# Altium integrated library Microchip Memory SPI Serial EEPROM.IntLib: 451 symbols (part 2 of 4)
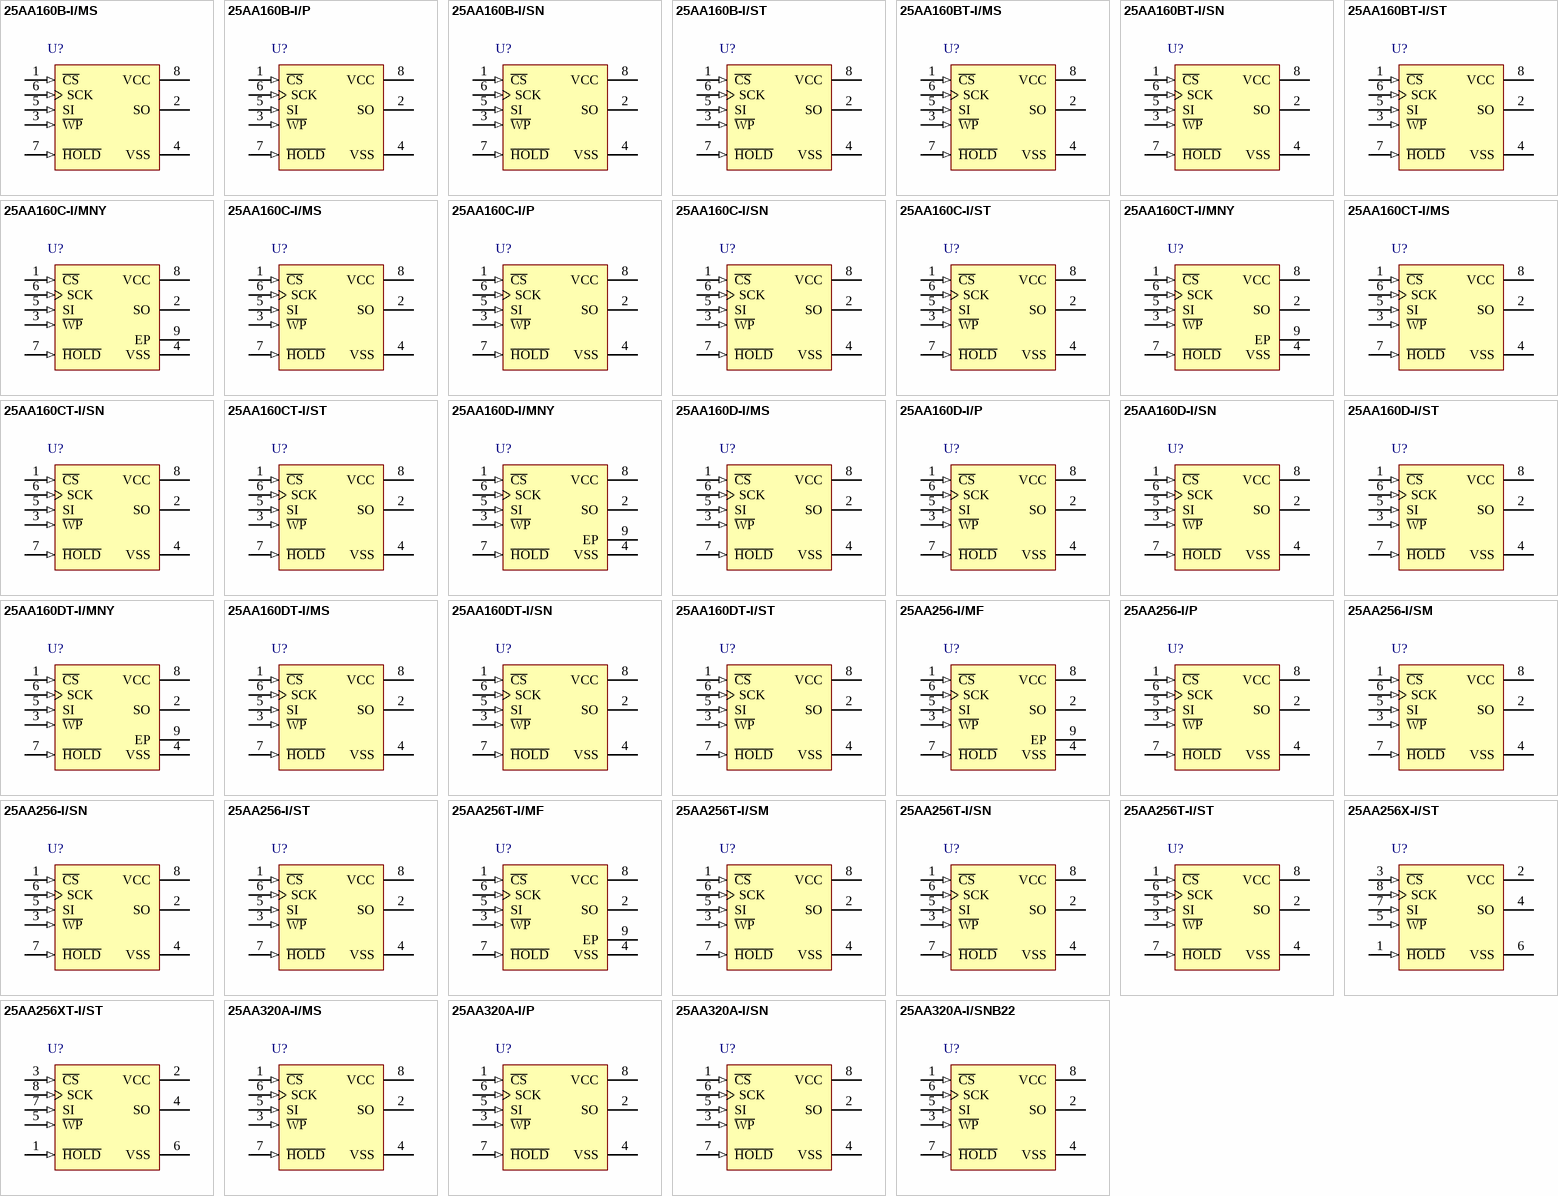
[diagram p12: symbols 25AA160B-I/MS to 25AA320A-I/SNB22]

## 25AA256T-I/SM
designator U?
256K SPI Bus Serial EEPROM, 8-Pin SOIC, Industrial Temperature, Tape and Reel
footprint SOIJ-SM8_N (SOP, 8-Leads, Body 5.2x5.2mm, Pitch 1.27mm, IPC Medium Density)
footprint SOIJ-SM8_L (SOP, 8-Leads, Body 5.2x5.2mm, Pitch 1.27mm, IPC High Density)
footprint SOIJ-SM8_M (SOP, 8-Leads, Body 5.2x5.2mm, Pitch 1.27mm, IPC Low Density)
pins: 1 ~{CS} (in), 2 SO (hiz), 3 ~{WP} (in), 4 VSS (power), 5 SI (in), 6 SCK (in), 7 ~{HOLD} (in), 8 VCC (power)

## 25AA256T-I/SN
designator U?
256K SPI Bus Serial EEPROM, 8-Pin SOIC, Industrial Temperature, Tape and Reel
footprint SOIC-SN8_N (SOIC, 8-Leads, Body 4.9x3.8mm, Pitch 1.27mm, IPC Medium Density)
footprint SOIC-SN8_L (SOIC, 8-Leads, Body 4.9x3.8mm, Pitch 1.27mm, IPC High Density)
footprint SOIC-SN8_M (SOIC, 8-Leads, Body 4.9x3.8mm, Pitch 1.27mm, IPC Low Density)
pins: 1 ~{CS} (in), 2 SO (hiz), 3 ~{WP} (in), 4 VSS (power), 5 SI (in), 6 SCK (in), 7 ~{HOLD} (in), 8 VCC (power)

## 25AA256T-I/ST
designator U?
256K SPI Bus Serial EEPROM, 8-Pin TSSOP, Industrial Temperature, Tape and Reel
footprint TSSOP-ST8_N (TSOP, 8-Leads, Body 3x4.4mm, Pitch 0.65mm, IPC Medium Density)
footprint TSSOP-ST8_L (TSOP, 8-Leads, Body 3x4.4mm, Pitch 0.65mm, IPC High Density)
footprint TSSOP-ST8_M (TSOP, 8-Leads, Body 3x4.4mm, Pitch 0.65mm, IPC Low Density)
pins: 1 ~{CS} (in), 2 SO (hiz), 3 ~{WP} (in), 4 VSS (power), 5 SI (in), 6 SCK (in), 7 ~{HOLD} (in), 8 VCC (power)

## 25AA256X-I/ST
designator U?
256K SPI Bus Serial EEPROM, 8-Pin TSSOP, Industrial Temperature
footprint TSSOP-ST8_N (TSOP, 8-Leads, Body 3x4.4mm, Pitch 0.65mm, IPC Medium Density)
footprint TSSOP-ST8_L (TSOP, 8-Leads, Body 3x4.4mm, Pitch 0.65mm, IPC High Density)
footprint TSSOP-ST8_M (TSOP, 8-Leads, Body 3x4.4mm, Pitch 0.65mm, IPC Low Density)
pins: 1 ~{HOLD} (in), 2 VCC (power), 3 ~{CS} (in), 4 SO (hiz), 5 ~{WP} (in), 6 VSS (power), 7 SI (in), 8 SCK (in)

## 25AA256XT-I/ST
designator U?
256K SPI Bus Serial EEPROM, 8-Pin TSSOP, Industrial Temperature, Tape and Reel
footprint TSSOP-ST8_N (TSOP, 8-Leads, Body 3x4.4mm, Pitch 0.65mm, IPC Medium Density)
footprint TSSOP-ST8_L (TSOP, 8-Leads, Body 3x4.4mm, Pitch 0.65mm, IPC High Density)
footprint TSSOP-ST8_M (TSOP, 8-Leads, Body 3x4.4mm, Pitch 0.65mm, IPC Low Density)
pins: 1 ~{HOLD} (in), 2 VCC (power), 3 ~{CS} (in), 4 SO (hiz), 5 ~{WP} (in), 6 VSS (power), 7 SI (in), 8 SCK (in)

## 25AA320A-I/MS
designator U?
32K SPI Bus Serial EEPROM, 8-Pin MSOP, Industrial Temperature
footprint MSOP-MS8_N (TSOP, 8-Leads, Body 3x3mm, Pitch 0.65mm, IPC Medium Density)
footprint MSOP-MS8_L (TSOP, 8-Leads, Body 3x3mm, Pitch 0.65mm, IPC High Density)
footprint MSOP-MS8_M (TSOP, 8-Leads, Body 3x3mm, Pitch 0.65mm, IPC Low Density)
pins: 1 ~{CS} (in), 2 SO (hiz), 3 ~{WP} (in), 4 VSS (power), 5 SI (in), 6 SCK (in), 7 ~{HOLD} (in), 8 VCC (power)

## 25AA320A-I/P
designator U?
32K SPI Bus Serial EEPROM, 8-Pin PDIP, Industrial Temperature
footprint PDIP300-P8 (DIP, 8-Leads, Row Spacing 7.62mm, Pitch 2.54mm, Body 9.5x6.6mm)
pins: 1 ~{CS} (in), 2 SO (hiz), 3 ~{WP} (in), 4 VSS (power), 5 SI (in), 6 SCK (in), 7 ~{HOLD} (in), 8 VCC (power)

## 25AA320A-I/SN
designator U?
32K SPI Bus Serial EEPROM, 8-Pin SOIC, Industrial Temperature
footprint SOIC-SN8_N (SOIC, 8-Leads, Body 4.9x3.8mm, Pitch 1.27mm, IPC Medium Density)
footprint SOIC-SN8_L (SOIC, 8-Leads, Body 4.9x3.8mm, Pitch 1.27mm, IPC High Density)
footprint SOIC-SN8_M (SOIC, 8-Leads, Body 4.9x3.8mm, Pitch 1.27mm, IPC Low Density)
pins: 1 ~{CS} (in), 2 SO (hiz), 3 ~{WP} (in), 4 VSS (power), 5 SI (in), 6 SCK (in), 7 ~{HOLD} (in), 8 VCC (power)

## 25AA320A-I/SNB22
designator U?
32K SPI Bus Serial EEPROM, 8-Pin SOIC, Industrial Temperature
footprint SOIC-SN8_N (SOIC, 8-Leads, Body 4.9x3.8mm, Pitch 1.27mm, IPC Medium Density)
footprint SOIC-SN8_L (SOIC, 8-Leads, Body 4.9x3.8mm, Pitch 1.27mm, IPC High Density)
footprint SOIC-SN8_M (SOIC, 8-Leads, Body 4.9x3.8mm, Pitch 1.27mm, IPC Low Density)
pins: 1 ~{CS} (in), 2 SO (hiz), 3 ~{WP} (in), 4 VSS (power), 5 SI (in), 6 SCK (in), 7 ~{HOLD} (in), 8 VCC (power)

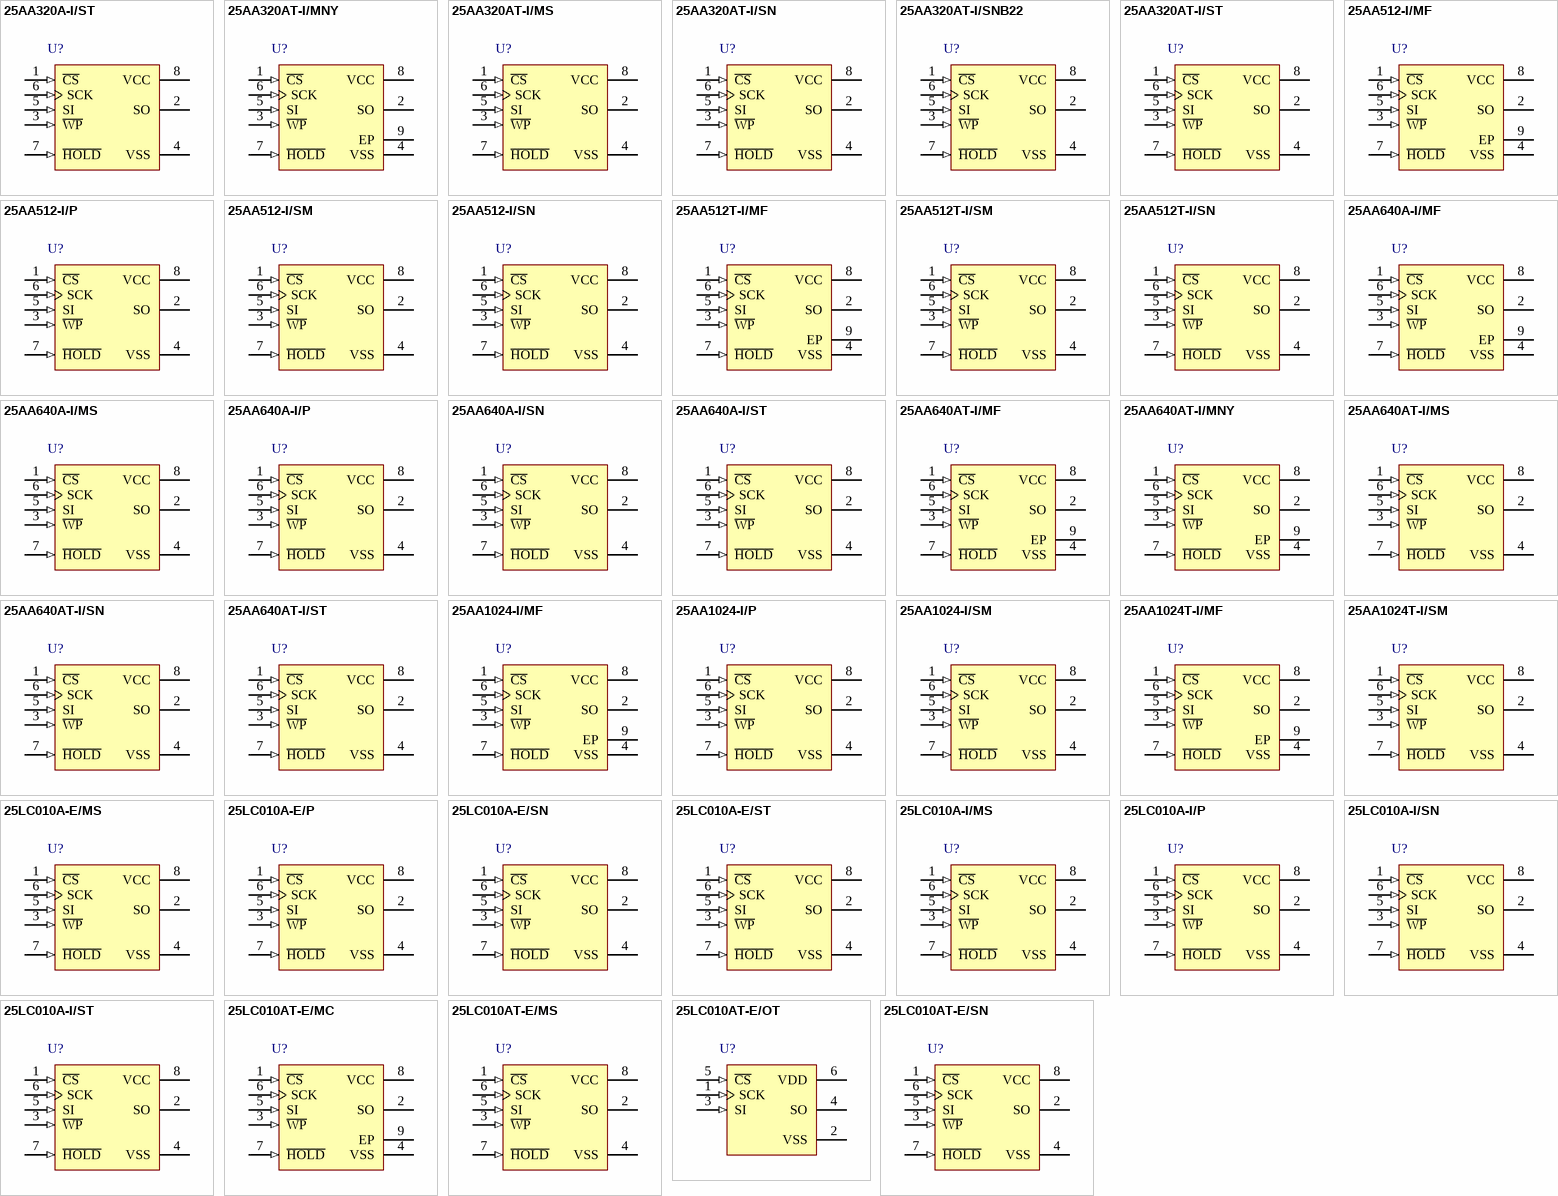
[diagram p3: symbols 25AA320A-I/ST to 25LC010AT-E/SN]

## 25AA320A-I/ST
designator U?
32K SPI Bus Serial EEPROM, 8-Pin TSSOP, Industrial Temperature
footprint TSSOP-ST8_N (TSOP, 8-Leads, Body 3x4.4mm, Pitch 0.65mm, IPC Medium Density)
footprint TSSOP-ST8_L (TSOP, 8-Leads, Body 3x4.4mm, Pitch 0.65mm, IPC High Density)
footprint TSSOP-ST8_M (TSOP, 8-Leads, Body 3x4.4mm, Pitch 0.65mm, IPC Low Density)
pins: 1 ~{CS} (in), 2 SO (hiz), 3 ~{WP} (in), 4 VSS (power), 5 SI (in), 6 SCK (in), 7 ~{HOLD} (in), 8 VCC (power)

## 25AA320AT-I/MNY
designator U?
32K SPI Bus Serial EEPROM, 8-Pin TDFN, Industrial Temperature, Tape and Reel
footprint TDFN-MN8 (SON, 8-Leads, Body 2x3mm, Pitch 0.5mm, Microchip Recommended)
pins: 1 ~{CS} (in), 2 SO (hiz), 3 ~{WP} (in), 4 VSS (power), 5 SI (in), 6 SCK (in), 7 ~{HOLD} (in), 8 VCC (power), 9 EP

## 25AA320AT-I/MS
designator U?
32K SPI Bus Serial EEPROM, 8-Pin MSOP, Industrial Temperature, Tape and Reel
footprint MSOP-MS8_N (TSOP, 8-Leads, Body 3x3mm, Pitch 0.65mm, IPC Medium Density)
footprint MSOP-MS8_L (TSOP, 8-Leads, Body 3x3mm, Pitch 0.65mm, IPC High Density)
footprint MSOP-MS8_M (TSOP, 8-Leads, Body 3x3mm, Pitch 0.65mm, IPC Low Density)
pins: 1 ~{CS} (in), 2 SO (hiz), 3 ~{WP} (in), 4 VSS (power), 5 SI (in), 6 SCK (in), 7 ~{HOLD} (in), 8 VCC (power)

## 25AA320AT-I/SN
designator U?
32K SPI Bus Serial EEPROM, 8-Pin SOIC, Industrial Temperature, Tape and Reel
footprint SOIC-SN8_N (SOIC, 8-Leads, Body 4.9x3.8mm, Pitch 1.27mm, IPC Medium Density)
footprint SOIC-SN8_L (SOIC, 8-Leads, Body 4.9x3.8mm, Pitch 1.27mm, IPC High Density)
footprint SOIC-SN8_M (SOIC, 8-Leads, Body 4.9x3.8mm, Pitch 1.27mm, IPC Low Density)
pins: 1 ~{CS} (in), 2 SO (hiz), 3 ~{WP} (in), 4 VSS (power), 5 SI (in), 6 SCK (in), 7 ~{HOLD} (in), 8 VCC (power)

## 25AA320AT-I/SNB22
designator U?
32K SPI Bus Serial EEPROM, 8-Pin SOIC, Industrial Temperature, Tape and Reel
footprint SOIC-SN8_N (SOIC, 8-Leads, Body 4.9x3.8mm, Pitch 1.27mm, IPC Medium Density)
footprint SOIC-SN8_L (SOIC, 8-Leads, Body 4.9x3.8mm, Pitch 1.27mm, IPC High Density)
footprint SOIC-SN8_M (SOIC, 8-Leads, Body 4.9x3.8mm, Pitch 1.27mm, IPC Low Density)
pins: 1 ~{CS} (in), 2 SO (hiz), 3 ~{WP} (in), 4 VSS (power), 5 SI (in), 6 SCK (in), 7 ~{HOLD} (in), 8 VCC (power)

## 25AA320AT-I/ST
designator U?
32K SPI Bus Serial EEPROM, 8-Pin TSSOP, Industrial Temperature, Tape and Reel
footprint TSSOP-ST8_N (TSOP, 8-Leads, Body 3x4.4mm, Pitch 0.65mm, IPC Medium Density)
footprint TSSOP-ST8_L (TSOP, 8-Leads, Body 3x4.4mm, Pitch 0.65mm, IPC High Density)
footprint TSSOP-ST8_M (TSOP, 8-Leads, Body 3x4.4mm, Pitch 0.65mm, IPC Low Density)
pins: 1 ~{CS} (in), 2 SO (hiz), 3 ~{WP} (in), 4 VSS (power), 5 SI (in), 6 SCK (in), 7 ~{HOLD} (in), 8 VCC (power)

## 25AA512-I/MF
designator U?
512 Kbit SPI Bus Serial EEPROM, 8-Pin DFN, Industrial Temperature
footprint DFNS-MF8_PS (SON, 8-Leads, Body 5x6mm, Pitch 1.27mm)
pins: 1 ~{CS} (in), 2 SO (hiz), 3 ~{WP} (in), 4 VSS (power), 5 SI (in), 6 SCK (in), 7 ~{HOLD} (in), 8 VCC (power), 9 EP

## 25AA512-I/P
designator U?
512 Kbit SPI Bus Serial EEPROM, 8-Pin PDIP, Industrial Temperature
footprint PDIP300-P8 (DIP, 8-Leads, Row Spacing 7.62mm, Pitch 2.54mm, Body 9.5x6.6mm)
pins: 1 ~{CS} (in), 2 SO (hiz), 3 ~{WP} (in), 4 VSS (power), 5 SI (in), 6 SCK (in), 7 ~{HOLD} (in), 8 VCC (power)

## 25AA512-I/SM
designator U?
512 Kbit SPI Bus Serial EEPROM, 8-Pin SOIC, Industrial Temperature
footprint SOIJ-SM8_N (SOP, 8-Leads, Body 5.2x5.2mm, Pitch 1.27mm, IPC Medium Density)
footprint SOIJ-SM8_L (SOP, 8-Leads, Body 5.2x5.2mm, Pitch 1.27mm, IPC High Density)
footprint SOIJ-SM8_M (SOP, 8-Leads, Body 5.2x5.2mm, Pitch 1.27mm, IPC Low Density)
pins: 1 ~{CS} (in), 2 SO (hiz), 3 ~{WP} (in), 4 VSS (power), 5 SI (in), 6 SCK (in), 7 ~{HOLD} (in), 8 VCC (power)

## 25AA512-I/SN
designator U?
512 Kbit SPI Bus Serial EEPROM, 8-Pin SOIC, Industrial Temperature
footprint SOIC-SN8_N (SOIC, 8-Leads, Body 4.9x3.8mm, Pitch 1.27mm, IPC Medium Density)
footprint SOIC-SN8_L (SOIC, 8-Leads, Body 4.9x3.8mm, Pitch 1.27mm, IPC High Density)
footprint SOIC-SN8_M (SOIC, 8-Leads, Body 4.9x3.8mm, Pitch 1.27mm, IPC Low Density)
pins: 1 ~{CS} (in), 2 SO (hiz), 3 ~{WP} (in), 4 VSS (power), 5 SI (in), 6 SCK (in), 7 ~{HOLD} (in), 8 VCC (power)

## 25AA512T-I/MF
designator U?
512 Kbit SPI Bus Serial EEPROM, 8-Pin DFN, Industrial Temperature, Tape and Reel
footprint DFNS-MF8_PS (SON, 8-Leads, Body 5x6mm, Pitch 1.27mm)
pins: 1 ~{CS} (in), 2 SO (hiz), 3 ~{WP} (in), 4 VSS (power), 5 SI (in), 6 SCK (in), 7 ~{HOLD} (in), 8 VCC (power), 9 EP

## 25AA512T-I/SM
designator U?
512 Kbit SPI Bus Serial EEPROM, 8-Pin SOIC, Industrial Temperature, Tape and Reel
footprint SOIJ-SM8_N (SOP, 8-Leads, Body 5.2x5.2mm, Pitch 1.27mm, IPC Medium Density)
footprint SOIJ-SM8_L (SOP, 8-Leads, Body 5.2x5.2mm, Pitch 1.27mm, IPC High Density)
footprint SOIJ-SM8_M (SOP, 8-Leads, Body 5.2x5.2mm, Pitch 1.27mm, IPC Low Density)
pins: 1 ~{CS} (in), 2 SO (hiz), 3 ~{WP} (in), 4 VSS (power), 5 SI (in), 6 SCK (in), 7 ~{HOLD} (in), 8 VCC (power)

## 25AA512T-I/SN
designator U?
512 Kbit SPI Bus Serial EEPROM, 8-Pin SOIC, Industrial Temperature, Tape and Reel
footprint SOIC-SN8_N (SOIC, 8-Leads, Body 4.9x3.8mm, Pitch 1.27mm, IPC Medium Density)
footprint SOIC-SN8_L (SOIC, 8-Leads, Body 4.9x3.8mm, Pitch 1.27mm, IPC High Density)
footprint SOIC-SN8_M (SOIC, 8-Leads, Body 4.9x3.8mm, Pitch 1.27mm, IPC Low Density)
pins: 1 ~{CS} (in), 2 SO (hiz), 3 ~{WP} (in), 4 VSS (power), 5 SI (in), 6 SCK (in), 7 ~{HOLD} (in), 8 VCC (power)

## 25AA640A-I/MF
designator U?
64K SPI Bus Serial EEPROM, 8-Pin DFN, Industrial Temperature
footprint DFNS-MF8_PS (SON, 8-Leads, Body 5x6mm, Pitch 1.27mm)
pins: 1 ~{CS} (in), 2 SO (hiz), 3 ~{WP} (in), 4 VSS (power), 5 SI (in), 6 SCK (in), 7 ~{HOLD} (in), 8 VCC (power), 9 EP

## 25AA640A-I/MS
designator U?
64K SPI Bus Serial EEPROM, 8-Pin MSOP, Industrial Temperature
footprint MSOP-MS8_N (TSOP, 8-Leads, Body 3x3mm, Pitch 0.65mm, IPC Medium Density)
footprint MSOP-MS8_L (TSOP, 8-Leads, Body 3x3mm, Pitch 0.65mm, IPC High Density)
footprint MSOP-MS8_M (TSOP, 8-Leads, Body 3x3mm, Pitch 0.65mm, IPC Low Density)
pins: 1 ~{CS} (in), 2 SO (hiz), 3 ~{WP} (in), 4 VSS (power), 5 SI (in), 6 SCK (in), 7 ~{HOLD} (in), 8 VCC (power)

## 25AA640A-I/P
designator U?
64K SPI Bus Serial EEPROM, 8-Pin PDIP, Industrial Temperature
footprint PDIP300-P8 (DIP, 8-Leads, Row Spacing 7.62mm, Pitch 2.54mm, Body 9.5x6.6mm)
pins: 1 ~{CS} (in), 2 SO (hiz), 3 ~{WP} (in), 4 VSS (power), 5 SI (in), 6 SCK (in), 7 ~{HOLD} (in), 8 VCC (power)

## 25AA640A-I/SN
designator U?
64K SPI Bus Serial EEPROM, 8-Pin SOIC, Industrial Temperature
footprint SOIC-SN8_N (SOIC, 8-Leads, Body 4.9x3.8mm, Pitch 1.27mm, IPC Medium Density)
footprint SOIC-SN8_L (SOIC, 8-Leads, Body 4.9x3.8mm, Pitch 1.27mm, IPC High Density)
footprint SOIC-SN8_M (SOIC, 8-Leads, Body 4.9x3.8mm, Pitch 1.27mm, IPC Low Density)
pins: 1 ~{CS} (in), 2 SO (hiz), 3 ~{WP} (in), 4 VSS (power), 5 SI (in), 6 SCK (in), 7 ~{HOLD} (in), 8 VCC (power)

## 25AA640A-I/ST
designator U?
64K SPI Bus Serial EEPROM, 8-Pin TSSOP, Industrial Temperature
footprint TSSOP-ST8_N (TSOP, 8-Leads, Body 3x4.4mm, Pitch 0.65mm, IPC Medium Density)
footprint TSSOP-ST8_L (TSOP, 8-Leads, Body 3x4.4mm, Pitch 0.65mm, IPC High Density)
footprint TSSOP-ST8_M (TSOP, 8-Leads, Body 3x4.4mm, Pitch 0.65mm, IPC Low Density)
pins: 1 ~{CS} (in), 2 SO (hiz), 3 ~{WP} (in), 4 VSS (power), 5 SI (in), 6 SCK (in), 7 ~{HOLD} (in), 8 VCC (power)

## 25AA640AT-I/MF
designator U?
64K SPI Bus Serial EEPROM, 8-Pin DFN, Industrial Temperature, Tape and Reel
footprint DFNS-MF8_PS (SON, 8-Leads, Body 5x6mm, Pitch 1.27mm)
pins: 1 ~{CS} (in), 2 SO (hiz), 3 ~{WP} (in), 4 VSS (power), 5 SI (in), 6 SCK (in), 7 ~{HOLD} (in), 8 VCC (power), 9 EP

## 25AA640AT-I/MNY
designator U?
64K SPI Bus Serial EEPROM, 8-Pin TDFN, Industrial Temperature, Tape and Reel
footprint TDFN-MN8 (SON, 8-Leads, Body 2x3mm, Pitch 0.5mm, Microchip Recommended)
pins: 1 ~{CS} (in), 2 SO (hiz), 3 ~{WP} (in), 4 VSS (power), 5 SI (in), 6 SCK (in), 7 ~{HOLD} (in), 8 VCC (power), 9 EP

## 25AA640AT-I/MS
designator U?
64K SPI Bus Serial EEPROM, 8-Pin MSOP, Industrial Temperature, Tape and Reel
footprint MSOP-MS8_N (TSOP, 8-Leads, Body 3x3mm, Pitch 0.65mm, IPC Medium Density)
footprint MSOP-MS8_L (TSOP, 8-Leads, Body 3x3mm, Pitch 0.65mm, IPC High Density)
footprint MSOP-MS8_M (TSOP, 8-Leads, Body 3x3mm, Pitch 0.65mm, IPC Low Density)
pins: 1 ~{CS} (in), 2 SO (hiz), 3 ~{WP} (in), 4 VSS (power), 5 SI (in), 6 SCK (in), 7 ~{HOLD} (in), 8 VCC (power)

## 25AA640AT-I/SN
designator U?
64K SPI Bus Serial EEPROM, 8-Pin SOIC, Industrial Temperature, Tape and Reel
footprint SOIC-SN8_N (SOIC, 8-Leads, Body 4.9x3.8mm, Pitch 1.27mm, IPC Medium Density)
footprint SOIC-SN8_L (SOIC, 8-Leads, Body 4.9x3.8mm, Pitch 1.27mm, IPC High Density)
footprint SOIC-SN8_M (SOIC, 8-Leads, Body 4.9x3.8mm, Pitch 1.27mm, IPC Low Density)
pins: 1 ~{CS} (in), 2 SO (hiz), 3 ~{WP} (in), 4 VSS (power), 5 SI (in), 6 SCK (in), 7 ~{HOLD} (in), 8 VCC (power)

## 25AA640AT-I/ST
designator U?
64K SPI Bus Serial EEPROM, 8-Pin TSSOP, Industrial Temperature, Tape and Reel
footprint TSSOP-ST8_N (TSOP, 8-Leads, Body 3x4.4mm, Pitch 0.65mm, IPC Medium Density)
footprint TSSOP-ST8_L (TSOP, 8-Leads, Body 3x4.4mm, Pitch 0.65mm, IPC High Density)
footprint TSSOP-ST8_M (TSOP, 8-Leads, Body 3x4.4mm, Pitch 0.65mm, IPC Low Density)
pins: 1 ~{CS} (in), 2 SO (hiz), 3 ~{WP} (in), 4 VSS (power), 5 SI (in), 6 SCK (in), 7 ~{HOLD} (in), 8 VCC (power)

## 25AA1024-I/MF
designator U?
1 Mbit SPI Bus Serial EEPROM, 8-Pin DFN, Industrial Temperature
footprint DFNS-MF8_PS (SON, 8-Leads, Body 5x6mm, Pitch 1.27mm)
pins: 1 ~{CS} (in), 2 SO (hiz), 3 ~{WP} (in), 4 VSS (power), 5 SI (in), 6 SCK (in), 7 ~{HOLD} (in), 8 VCC (power), 9 EP

## 25AA1024-I/P
designator U?
1 Mbit SPI Bus Serial EEPROM, 8-Pin PDIP, Industrial Temperature
footprint PDIP300-P8 (DIP, 8-Leads, Row Spacing 7.62mm, Pitch 2.54mm, Body 9.5x6.6mm)
pins: 1 ~{CS} (in), 2 SO (hiz), 3 ~{WP} (in), 4 VSS (power), 5 SI (in), 6 SCK (in), 7 ~{HOLD} (in), 8 VCC (power)

## 25AA1024-I/SM
designator U?
1 Mbit SPI Bus Serial EEPROM, 8-Pin SOIC, Industrial Temperature
footprint SOIJ-SM8_N (SOP, 8-Leads, Body 5.2x5.2mm, Pitch 1.27mm, IPC Medium Density)
footprint SOIJ-SM8_L (SOP, 8-Leads, Body 5.2x5.2mm, Pitch 1.27mm, IPC High Density)
footprint SOIJ-SM8_M (SOP, 8-Leads, Body 5.2x5.2mm, Pitch 1.27mm, IPC Low Density)
pins: 1 ~{CS} (in), 2 SO (hiz), 3 ~{WP} (in), 4 VSS (power), 5 SI (in), 6 SCK (in), 7 ~{HOLD} (in), 8 VCC (power)

## 25AA1024T-I/MF
designator U?
1 Mbit SPI Bus Serial EEPROM, 8-Pin DFN, Industrial Temperature, Tape and Reel
footprint DFNS-MF8_PS (SON, 8-Leads, Body 5x6mm, Pitch 1.27mm)
pins: 1 ~{CS} (in), 2 SO (hiz), 3 ~{WP} (in), 4 VSS (power), 5 SI (in), 6 SCK (in), 7 ~{HOLD} (in), 8 VCC (power), 9 EP

## 25AA1024T-I/SM
designator U?
1 Mbit SPI Bus Serial EEPROM, 8-Pin SOIC, Industrial Temperature, Tape and Reel
footprint SOIJ-SM8_N (SOP, 8-Leads, Body 5.2x5.2mm, Pitch 1.27mm, IPC Medium Density)
footprint SOIJ-SM8_L (SOP, 8-Leads, Body 5.2x5.2mm, Pitch 1.27mm, IPC High Density)
footprint SOIJ-SM8_M (SOP, 8-Leads, Body 5.2x5.2mm, Pitch 1.27mm, IPC Low Density)
pins: 1 ~{CS} (in), 2 SO (hiz), 3 ~{WP} (in), 4 VSS (power), 5 SI (in), 6 SCK (in), 7 ~{HOLD} (in), 8 VCC (power)

## 25LC010A-E/MS
designator U?
1K SPI Bus Serial EEPROM, 8-Pin MSOP, Extended Temperature
footprint MSOP-MS8_N (TSOP, 8-Leads, Body 3x3mm, Pitch 0.65mm, IPC Medium Density)
footprint MSOP-MS8_L (TSOP, 8-Leads, Body 3x3mm, Pitch 0.65mm, IPC High Density)
footprint MSOP-MS8_M (TSOP, 8-Leads, Body 3x3mm, Pitch 0.65mm, IPC Low Density)
pins: 1 ~{CS} (in), 2 SO (hiz), 3 ~{WP} (in), 4 VSS (power), 5 SI (in), 6 SCK (in), 7 ~{HOLD} (in), 8 VCC (power)

## 25LC010A-E/P
designator U?
1K SPI Bus Serial EEPROM, 8-Pin PDIP, Extended Temperature
footprint PDIP300-P8 (DIP, 8-Leads, Row Spacing 7.62mm, Pitch 2.54mm, Body 9.5x6.6mm)
pins: 1 ~{CS} (in), 2 SO (hiz), 3 ~{WP} (in), 4 VSS (power), 5 SI (in), 6 SCK (in), 7 ~{HOLD} (in), 8 VCC (power)

## 25LC010A-E/SN
designator U?
1K SPI Bus Serial EEPROM, 8-Pin SOIC, Extended Temperature
footprint SOIC-SN8_N (SOIC, 8-Leads, Body 4.9x3.8mm, Pitch 1.27mm, IPC Medium Density)
footprint SOIC-SN8_L (SOIC, 8-Leads, Body 4.9x3.8mm, Pitch 1.27mm, IPC High Density)
footprint SOIC-SN8_M (SOIC, 8-Leads, Body 4.9x3.8mm, Pitch 1.27mm, IPC Low Density)
pins: 1 ~{CS} (in), 2 SO (hiz), 3 ~{WP} (in), 4 VSS (power), 5 SI (in), 6 SCK (in), 7 ~{HOLD} (in), 8 VCC (power)

## 25LC010A-E/ST
designator U?
1K SPI Bus Serial EEPROM, 8-Pin TSSOP, Extended Temperature
footprint TSSOP-ST8_N (TSOP, 8-Leads, Body 3x4.4mm, Pitch 0.65mm, IPC Medium Density)
footprint TSSOP-ST8_L (TSOP, 8-Leads, Body 3x4.4mm, Pitch 0.65mm, IPC High Density)
footprint TSSOP-ST8_M (TSOP, 8-Leads, Body 3x4.4mm, Pitch 0.65mm, IPC Low Density)
pins: 1 ~{CS} (in), 2 SO (hiz), 3 ~{WP} (in), 4 VSS (power), 5 SI (in), 6 SCK (in), 7 ~{HOLD} (in), 8 VCC (power)

## 25LC010A-I/MS
designator U?
1K SPI Bus Serial EEPROM, 8-Pin MSOP, Industrial Temperature
footprint MSOP-MS8_N (TSOP, 8-Leads, Body 3x3mm, Pitch 0.65mm, IPC Medium Density)
footprint MSOP-MS8_L (TSOP, 8-Leads, Body 3x3mm, Pitch 0.65mm, IPC High Density)
footprint MSOP-MS8_M (TSOP, 8-Leads, Body 3x3mm, Pitch 0.65mm, IPC Low Density)
pins: 1 ~{CS} (in), 2 SO (hiz), 3 ~{WP} (in), 4 VSS (power), 5 SI (in), 6 SCK (in), 7 ~{HOLD} (in), 8 VCC (power)

## 25LC010A-I/P
designator U?
1K SPI Bus Serial EEPROM, 8-Pin PDIP, Industrial Temperature
footprint PDIP300-P8 (DIP, 8-Leads, Row Spacing 7.62mm, Pitch 2.54mm, Body 9.5x6.6mm)
pins: 1 ~{CS} (in), 2 SO (hiz), 3 ~{WP} (in), 4 VSS (power), 5 SI (in), 6 SCK (in), 7 ~{HOLD} (in), 8 VCC (power)

## 25LC010A-I/SN
designator U?
1K SPI Bus Serial EEPROM, 8-Pin SOIC, Industrial Temperature
footprint SOIC-SN8_N (SOIC, 8-Leads, Body 4.9x3.8mm, Pitch 1.27mm, IPC Medium Density)
footprint SOIC-SN8_L (SOIC, 8-Leads, Body 4.9x3.8mm, Pitch 1.27mm, IPC High Density)
footprint SOIC-SN8_M (SOIC, 8-Leads, Body 4.9x3.8mm, Pitch 1.27mm, IPC Low Density)
pins: 1 ~{CS} (in), 2 SO (hiz), 3 ~{WP} (in), 4 VSS (power), 5 SI (in), 6 SCK (in), 7 ~{HOLD} (in), 8 VCC (power)

## 25LC010A-I/ST
designator U?
1K SPI Bus Serial EEPROM, 8-Pin TSSOP, Industrial Temperature
footprint TSSOP-ST8_N (TSOP, 8-Leads, Body 3x4.4mm, Pitch 0.65mm, IPC Medium Density)
footprint TSSOP-ST8_L (TSOP, 8-Leads, Body 3x4.4mm, Pitch 0.65mm, IPC High Density)
footprint TSSOP-ST8_M (TSOP, 8-Leads, Body 3x4.4mm, Pitch 0.65mm, IPC Low Density)
pins: 1 ~{CS} (in), 2 SO (hiz), 3 ~{WP} (in), 4 VSS (power), 5 SI (in), 6 SCK (in), 7 ~{HOLD} (in), 8 VCC (power)

## 25LC010AT-E/MC
designator U?
1K SPI Bus Serial EEPROM, 8-Pin DFN, Extended Temperature, Tape and Reel
footprint DFN-MC8 (SON, 8-Leads, Body 2x3mm, Pitch 0.5mm, Microchip Recommended)
pins: 1 ~{CS} (in), 2 SO (hiz), 3 ~{WP} (in), 4 VSS (power), 5 SI (in), 6 SCK (in), 7 ~{HOLD} (in), 8 VCC (power), 9 EP

## 25LC010AT-E/MS
designator U?
1K SPI Bus Serial EEPROM, 8-Pin MSOP, Extended Temperature, Tape and Reel
footprint MSOP-MS8_N (TSOP, 8-Leads, Body 3x3mm, Pitch 0.65mm, IPC Medium Density)
footprint MSOP-MS8_L (TSOP, 8-Leads, Body 3x3mm, Pitch 0.65mm, IPC High Density)
footprint MSOP-MS8_M (TSOP, 8-Leads, Body 3x3mm, Pitch 0.65mm, IPC Low Density)
pins: 1 ~{CS} (in), 2 SO (hiz), 3 ~{WP} (in), 4 VSS (power), 5 SI (in), 6 SCK (in), 7 ~{HOLD} (in), 8 VCC (power)

## 25LC010AT-E/OT
designator U?
1K SPI Bus Serial EEPROM, 6-Pin SOT-23, Extended Temperature, Tape and Reel
footprint SOT-23-OT6_N (SOT23, 6-Leads, Body 2.9x1.6mm, Pitch 0.95mm, Lead Span 2.7mm, IPC Medium Density)
footprint SOT-23-OT6_L (SOT23, 6-Leads, Body 2.9x1.6mm, Pitch 0.95mm, Lead Span 2.7mm, IPC High Density)
footprint SOT-23-OT6_M (SOT23, 6-Leads, Body 2.9x1.6mm, Pitch 0.95mm, Lead Span 2.7mm, IPC Low Density)
pins: 1 SCK (in), 2 VSS (power), 3 SI (in), 4 SO (hiz), 5 ~{CS} (in), 6 VDD (power)

## 25LC010AT-E/SN
designator U?
1K SPI Bus Serial EEPROM, 8-Pin SOIC, Extended Temperature, Tape and Reel
footprint SOIC-SN8_N (SOIC, 8-Leads, Body 4.9x3.8mm, Pitch 1.27mm, IPC Medium Density)
footprint SOIC-SN8_L (SOIC, 8-Leads, Body 4.9x3.8mm, Pitch 1.27mm, IPC High Density)
footprint SOIC-SN8_M (SOIC, 8-Leads, Body 4.9x3.8mm, Pitch 1.27mm, IPC Low Density)
pins: 1 ~{CS} (in), 2 SO (hiz), 3 ~{WP} (in), 4 VSS (power), 5 SI (in), 6 SCK (in), 7 ~{HOLD} (in), 8 VCC (power)

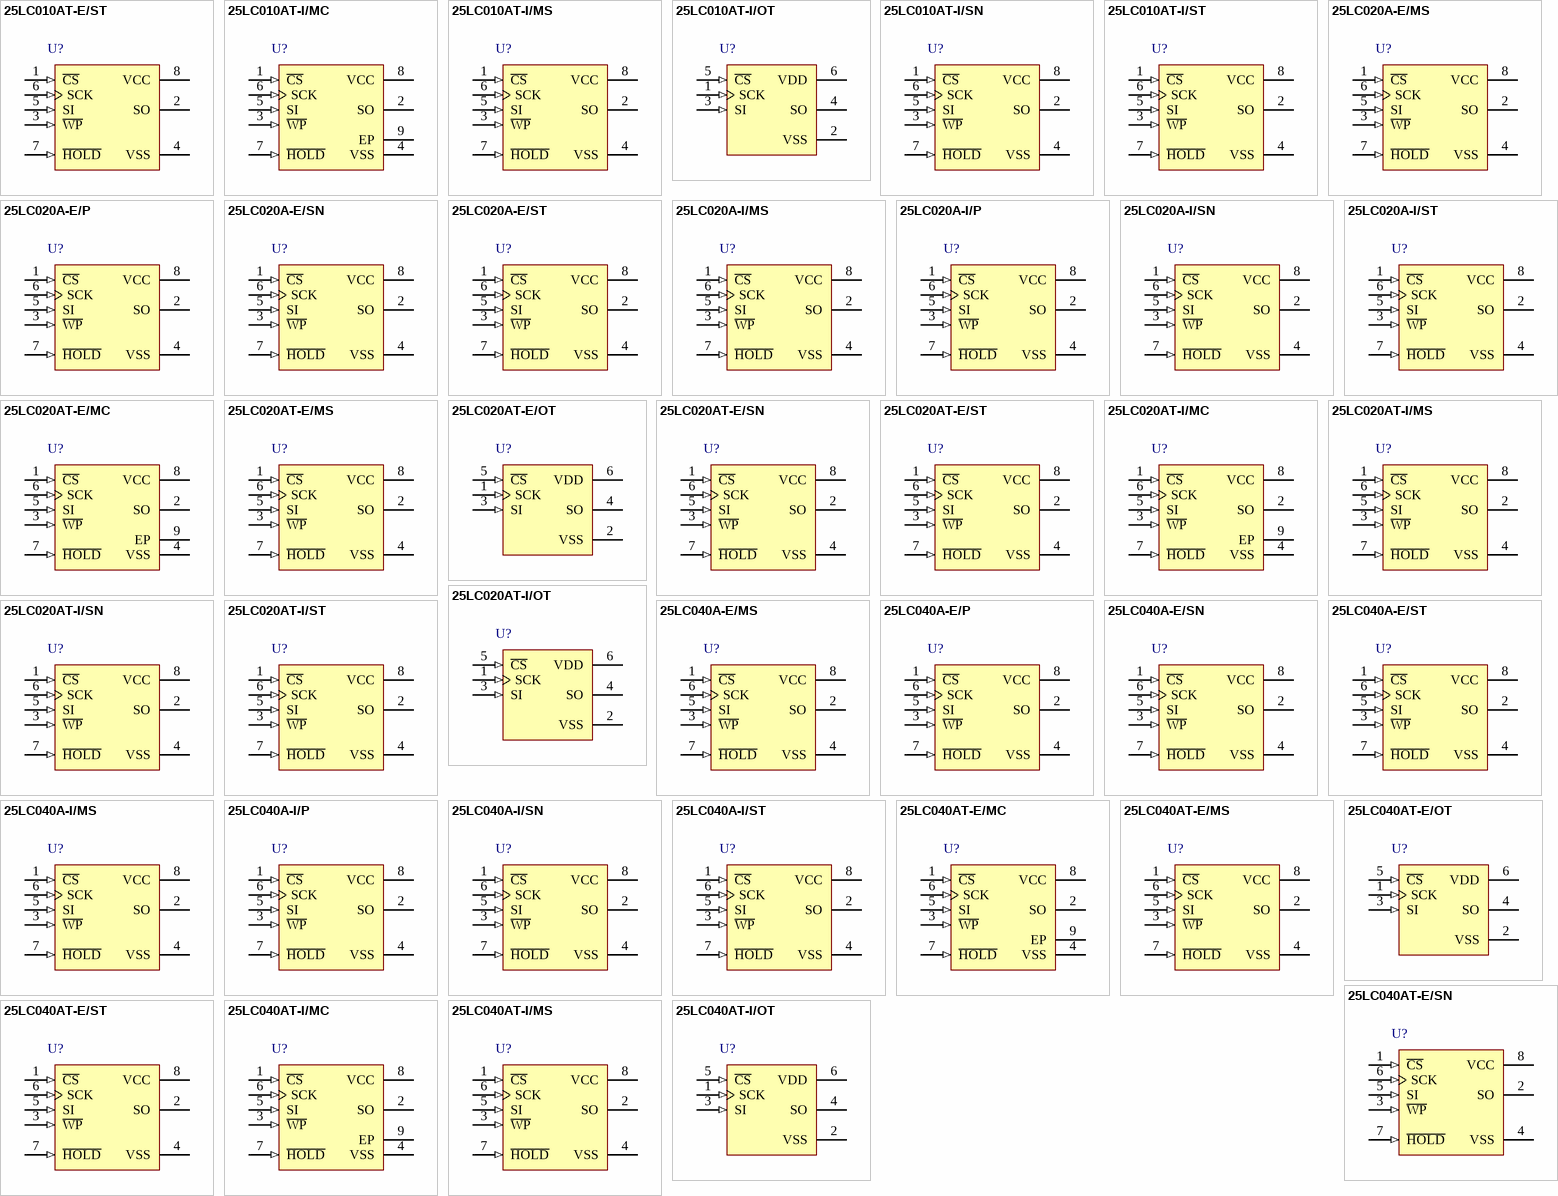
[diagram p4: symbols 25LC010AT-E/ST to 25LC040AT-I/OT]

## 25LC010AT-E/ST
designator U?
1K SPI Bus Serial EEPROM, 8-Pin TSSOP, Extended Temperature, Tape and Reel
footprint TSSOP-ST8_N (TSOP, 8-Leads, Body 3x4.4mm, Pitch 0.65mm, IPC Medium Density)
footprint TSSOP-ST8_L (TSOP, 8-Leads, Body 3x4.4mm, Pitch 0.65mm, IPC High Density)
footprint TSSOP-ST8_M (TSOP, 8-Leads, Body 3x4.4mm, Pitch 0.65mm, IPC Low Density)
pins: 1 ~{CS} (in), 2 SO (hiz), 3 ~{WP} (in), 4 VSS (power), 5 SI (in), 6 SCK (in), 7 ~{HOLD} (in), 8 VCC (power)

## 25LC010AT-I/MC
designator U?
1K SPI Bus Serial EEPROM, 8-Pin DFN, Industrial Temperature, Tape and Reel
footprint DFN-MC8 (SON, 8-Leads, Body 2x3mm, Pitch 0.5mm, Microchip Recommended)
pins: 1 ~{CS} (in), 2 SO (hiz), 3 ~{WP} (in), 4 VSS (power), 5 SI (in), 6 SCK (in), 7 ~{HOLD} (in), 8 VCC (power), 9 EP

## 25LC010AT-I/MS
designator U?
1K SPI Bus Serial EEPROM, 8-Pin MSOP, Industrial Temperature, Tape and Reel
footprint MSOP-MS8_N (TSOP, 8-Leads, Body 3x3mm, Pitch 0.65mm, IPC Medium Density)
footprint MSOP-MS8_L (TSOP, 8-Leads, Body 3x3mm, Pitch 0.65mm, IPC High Density)
footprint MSOP-MS8_M (TSOP, 8-Leads, Body 3x3mm, Pitch 0.65mm, IPC Low Density)
pins: 1 ~{CS} (in), 2 SO (hiz), 3 ~{WP} (in), 4 VSS (power), 5 SI (in), 6 SCK (in), 7 ~{HOLD} (in), 8 VCC (power)

## 25LC010AT-I/OT
designator U?
1K SPI Bus Serial EEPROM, 6-Pin SOT-23, Industrial Temperature, Tape and Reel
footprint SOT-23-OT6_N (SOT23, 6-Leads, Body 2.9x1.6mm, Pitch 0.95mm, Lead Span 2.7mm, IPC Medium Density)
footprint SOT-23-OT6_L (SOT23, 6-Leads, Body 2.9x1.6mm, Pitch 0.95mm, Lead Span 2.7mm, IPC High Density)
footprint SOT-23-OT6_M (SOT23, 6-Leads, Body 2.9x1.6mm, Pitch 0.95mm, Lead Span 2.7mm, IPC Low Density)
pins: 1 SCK (in), 2 VSS (power), 3 SI (in), 4 SO (hiz), 5 ~{CS} (in), 6 VDD (power)

## 25LC010AT-I/SN
designator U?
1K SPI Bus Serial EEPROM, 8-Pin SOIC, Industrial Temperature, Tape and Reel
footprint SOIC-SN8_N (SOIC, 8-Leads, Body 4.9x3.8mm, Pitch 1.27mm, IPC Medium Density)
footprint SOIC-SN8_L (SOIC, 8-Leads, Body 4.9x3.8mm, Pitch 1.27mm, IPC High Density)
footprint SOIC-SN8_M (SOIC, 8-Leads, Body 4.9x3.8mm, Pitch 1.27mm, IPC Low Density)
pins: 1 ~{CS} (in), 2 SO (hiz), 3 ~{WP} (in), 4 VSS (power), 5 SI (in), 6 SCK (in), 7 ~{HOLD} (in), 8 VCC (power)

## 25LC010AT-I/ST
designator U?
1K SPI Bus Serial EEPROM, 8-Pin TSSOP, Industrial Temperature, Tape and Reel
footprint TSSOP-ST8_N (TSOP, 8-Leads, Body 3x4.4mm, Pitch 0.65mm, IPC Medium Density)
footprint TSSOP-ST8_L (TSOP, 8-Leads, Body 3x4.4mm, Pitch 0.65mm, IPC High Density)
footprint TSSOP-ST8_M (TSOP, 8-Leads, Body 3x4.4mm, Pitch 0.65mm, IPC Low Density)
pins: 1 ~{CS} (in), 2 SO (hiz), 3 ~{WP} (in), 4 VSS (power), 5 SI (in), 6 SCK (in), 7 ~{HOLD} (in), 8 VCC (power)

## 25LC020A-E/MS
designator U?
2K SPI Bus Serial EEPROM, 8-Pin MSOP, Extended Temperature
footprint MSOP-MS8_N (TSOP, 8-Leads, Body 3x3mm, Pitch 0.65mm, IPC Medium Density)
footprint MSOP-MS8_L (TSOP, 8-Leads, Body 3x3mm, Pitch 0.65mm, IPC High Density)
footprint MSOP-MS8_M (TSOP, 8-Leads, Body 3x3mm, Pitch 0.65mm, IPC Low Density)
pins: 1 ~{CS} (in), 2 SO (hiz), 3 ~{WP} (in), 4 VSS (power), 5 SI (in), 6 SCK (in), 7 ~{HOLD} (in), 8 VCC (power)

## 25LC020A-E/P
designator U?
2K SPI Bus Serial EEPROM, 8-Pin PDIP, Extended Temperature
footprint PDIP300-P8 (DIP, 8-Leads, Row Spacing 7.62mm, Pitch 2.54mm, Body 9.5x6.6mm)
pins: 1 ~{CS} (in), 2 SO (hiz), 3 ~{WP} (in), 4 VSS (power), 5 SI (in), 6 SCK (in), 7 ~{HOLD} (in), 8 VCC (power)

## 25LC020A-E/SN
designator U?
2K SPI Bus Serial EEPROM, 8-Pin SOIC, Extended Temperature
footprint SOIC-SN8_N (SOIC, 8-Leads, Body 4.9x3.8mm, Pitch 1.27mm, IPC Medium Density)
footprint SOIC-SN8_L (SOIC, 8-Leads, Body 4.9x3.8mm, Pitch 1.27mm, IPC High Density)
footprint SOIC-SN8_M (SOIC, 8-Leads, Body 4.9x3.8mm, Pitch 1.27mm, IPC Low Density)
pins: 1 ~{CS} (in), 2 SO (hiz), 3 ~{WP} (in), 4 VSS (power), 5 SI (in), 6 SCK (in), 7 ~{HOLD} (in), 8 VCC (power)

## 25LC020A-E/ST
designator U?
2K SPI Bus Serial EEPROM, 8-Pin TSSOP, Extended Temperature
footprint TSSOP-ST8_N (TSOP, 8-Leads, Body 3x4.4mm, Pitch 0.65mm, IPC Medium Density)
footprint TSSOP-ST8_L (TSOP, 8-Leads, Body 3x4.4mm, Pitch 0.65mm, IPC High Density)
footprint TSSOP-ST8_M (TSOP, 8-Leads, Body 3x4.4mm, Pitch 0.65mm, IPC Low Density)
pins: 1 ~{CS} (in), 2 SO (hiz), 3 ~{WP} (in), 4 VSS (power), 5 SI (in), 6 SCK (in), 7 ~{HOLD} (in), 8 VCC (power)

## 25LC020A-I/MS
designator U?
2K SPI Bus Serial EEPROM, 8-Pin MSOP, Industrial Temperature
footprint MSOP-MS8_N (TSOP, 8-Leads, Body 3x3mm, Pitch 0.65mm, IPC Medium Density)
footprint MSOP-MS8_L (TSOP, 8-Leads, Body 3x3mm, Pitch 0.65mm, IPC High Density)
footprint MSOP-MS8_M (TSOP, 8-Leads, Body 3x3mm, Pitch 0.65mm, IPC Low Density)
pins: 1 ~{CS} (in), 2 SO (hiz), 3 ~{WP} (in), 4 VSS (power), 5 SI (in), 6 SCK (in), 7 ~{HOLD} (in), 8 VCC (power)

## 25LC020A-I/P
designator U?
2K SPI Bus Serial EEPROM, 8-Pin PDIP, Industrial Temperature
footprint PDIP300-P8 (DIP, 8-Leads, Row Spacing 7.62mm, Pitch 2.54mm, Body 9.5x6.6mm)
pins: 1 ~{CS} (in), 2 SO (hiz), 3 ~{WP} (in), 4 VSS (power), 5 SI (in), 6 SCK (in), 7 ~{HOLD} (in), 8 VCC (power)

## 25LC020A-I/SN
designator U?
2K SPI Bus Serial EEPROM, 8-Pin SOIC, Industrial Temperature
footprint SOIC-SN8_N (SOIC, 8-Leads, Body 4.9x3.8mm, Pitch 1.27mm, IPC Medium Density)
footprint SOIC-SN8_L (SOIC, 8-Leads, Body 4.9x3.8mm, Pitch 1.27mm, IPC High Density)
footprint SOIC-SN8_M (SOIC, 8-Leads, Body 4.9x3.8mm, Pitch 1.27mm, IPC Low Density)
pins: 1 ~{CS} (in), 2 SO (hiz), 3 ~{WP} (in), 4 VSS (power), 5 SI (in), 6 SCK (in), 7 ~{HOLD} (in), 8 VCC (power)

## 25LC020A-I/ST
designator U?
2K SPI Bus Serial EEPROM, 8-Pin TSSOP, Industrial Temperature
footprint TSSOP-ST8_N (TSOP, 8-Leads, Body 3x4.4mm, Pitch 0.65mm, IPC Medium Density)
footprint TSSOP-ST8_L (TSOP, 8-Leads, Body 3x4.4mm, Pitch 0.65mm, IPC High Density)
footprint TSSOP-ST8_M (TSOP, 8-Leads, Body 3x4.4mm, Pitch 0.65mm, IPC Low Density)
pins: 1 ~{CS} (in), 2 SO (hiz), 3 ~{WP} (in), 4 VSS (power), 5 SI (in), 6 SCK (in), 7 ~{HOLD} (in), 8 VCC (power)

## 25LC020AT-E/MC
designator U?
2K SPI Bus Serial EEPROM, 8-Pin DFN, Extended Temperature, Tape and Reel
footprint DFN-MC8 (SON, 8-Leads, Body 2x3mm, Pitch 0.5mm, Microchip Recommended)
pins: 1 ~{CS} (in), 2 SO (hiz), 3 ~{WP} (in), 4 VSS (power), 5 SI (in), 6 SCK (in), 7 ~{HOLD} (in), 8 VCC (power), 9 EP

## 25LC020AT-E/MS
designator U?
2K SPI Bus Serial EEPROM, 8-Pin MSOP, Extended Temperature, Tape and Reel
footprint MSOP-MS8_N (TSOP, 8-Leads, Body 3x3mm, Pitch 0.65mm, IPC Medium Density)
footprint MSOP-MS8_L (TSOP, 8-Leads, Body 3x3mm, Pitch 0.65mm, IPC High Density)
footprint MSOP-MS8_M (TSOP, 8-Leads, Body 3x3mm, Pitch 0.65mm, IPC Low Density)
pins: 1 ~{CS} (in), 2 SO (hiz), 3 ~{WP} (in), 4 VSS (power), 5 SI (in), 6 SCK (in), 7 ~{HOLD} (in), 8 VCC (power)

## 25LC020AT-E/OT
designator U?
2K SPI Bus Serial EEPROM, 6-Pin SOT-23, Extended Temperature, Tape and Reel
footprint SOT-23-OT6_N (SOT23, 6-Leads, Body 2.9x1.6mm, Pitch 0.95mm, Lead Span 2.7mm, IPC Medium Density)
footprint SOT-23-OT6_L (SOT23, 6-Leads, Body 2.9x1.6mm, Pitch 0.95mm, Lead Span 2.7mm, IPC High Density)
footprint SOT-23-OT6_M (SOT23, 6-Leads, Body 2.9x1.6mm, Pitch 0.95mm, Lead Span 2.7mm, IPC Low Density)
pins: 1 SCK (in), 2 VSS (power), 3 SI (in), 4 SO (hiz), 5 ~{CS} (in), 6 VDD (power)

## 25LC020AT-E/SN
designator U?
2K SPI Bus Serial EEPROM, 8-Pin SOIC, Extended Temperature, Tape and Reel
footprint SOIC-SN8_N (SOIC, 8-Leads, Body 4.9x3.8mm, Pitch 1.27mm, IPC Medium Density)
footprint SOIC-SN8_L (SOIC, 8-Leads, Body 4.9x3.8mm, Pitch 1.27mm, IPC High Density)
footprint SOIC-SN8_M (SOIC, 8-Leads, Body 4.9x3.8mm, Pitch 1.27mm, IPC Low Density)
pins: 1 ~{CS} (in), 2 SO (hiz), 3 ~{WP} (in), 4 VSS (power), 5 SI (in), 6 SCK (in), 7 ~{HOLD} (in), 8 VCC (power)

## 25LC020AT-E/ST
designator U?
2K SPI Bus Serial EEPROM, 8-Pin TSSOP, Extended Temperature, Tape and Reel
footprint TSSOP-ST8_N (TSOP, 8-Leads, Body 3x4.4mm, Pitch 0.65mm, IPC Medium Density)
footprint TSSOP-ST8_L (TSOP, 8-Leads, Body 3x4.4mm, Pitch 0.65mm, IPC High Density)
footprint TSSOP-ST8_M (TSOP, 8-Leads, Body 3x4.4mm, Pitch 0.65mm, IPC Low Density)
pins: 1 ~{CS} (in), 2 SO (hiz), 3 ~{WP} (in), 4 VSS (power), 5 SI (in), 6 SCK (in), 7 ~{HOLD} (in), 8 VCC (power)

## 25LC020AT-I/MC
designator U?
2K SPI Bus Serial EEPROM, 8-Pin DFN, Industrial Temperature, Tape and Reel
footprint DFN-MC8 (SON, 8-Leads, Body 2x3mm, Pitch 0.5mm, Microchip Recommended)
pins: 1 ~{CS} (in), 2 SO (hiz), 3 ~{WP} (in), 4 VSS (power), 5 SI (in), 6 SCK (in), 7 ~{HOLD} (in), 8 VCC (power), 9 EP

## 25LC020AT-I/MS
designator U?
2K SPI Bus Serial EEPROM, 8-Pin MSOP, Industrial Temperature, Tape and Reel
footprint MSOP-MS8_N (TSOP, 8-Leads, Body 3x3mm, Pitch 0.65mm, IPC Medium Density)
footprint MSOP-MS8_L (TSOP, 8-Leads, Body 3x3mm, Pitch 0.65mm, IPC High Density)
footprint MSOP-MS8_M (TSOP, 8-Leads, Body 3x3mm, Pitch 0.65mm, IPC Low Density)
pins: 1 ~{CS} (in), 2 SO (hiz), 3 ~{WP} (in), 4 VSS (power), 5 SI (in), 6 SCK (in), 7 ~{HOLD} (in), 8 VCC (power)

## 25LC020AT-I/OT
designator U?
2K SPI Bus Serial EEPROM, 6-Pin SOT-23, Industrial Temperature, Tape and Reel
footprint SOT-23-OT6_N (SOT23, 6-Leads, Body 2.9x1.6mm, Pitch 0.95mm, Lead Span 2.7mm, IPC Medium Density)
footprint SOT-23-OT6_L (SOT23, 6-Leads, Body 2.9x1.6mm, Pitch 0.95mm, Lead Span 2.7mm, IPC High Density)
footprint SOT-23-OT6_M (SOT23, 6-Leads, Body 2.9x1.6mm, Pitch 0.95mm, Lead Span 2.7mm, IPC Low Density)
pins: 1 SCK (in), 2 VSS (power), 3 SI (in), 4 SO (hiz), 5 ~{CS} (in), 6 VDD (power)

## 25LC020AT-I/SN
designator U?
2K SPI Bus Serial EEPROM, 8-Pin SOIC, Industrial Temperature, Tape and Reel
footprint SOIC-SN8_N (SOIC, 8-Leads, Body 4.9x3.8mm, Pitch 1.27mm, IPC Medium Density)
footprint SOIC-SN8_L (SOIC, 8-Leads, Body 4.9x3.8mm, Pitch 1.27mm, IPC High Density)
footprint SOIC-SN8_M (SOIC, 8-Leads, Body 4.9x3.8mm, Pitch 1.27mm, IPC Low Density)
pins: 1 ~{CS} (in), 2 SO (hiz), 3 ~{WP} (in), 4 VSS (power), 5 SI (in), 6 SCK (in), 7 ~{HOLD} (in), 8 VCC (power)

## 25LC020AT-I/ST
designator U?
2K SPI Bus Serial EEPROM, 8-Pin TSSOP, Industrial Temperature, Tape and Reel
footprint TSSOP-ST8_N (TSOP, 8-Leads, Body 3x4.4mm, Pitch 0.65mm, IPC Medium Density)
footprint TSSOP-ST8_L (TSOP, 8-Leads, Body 3x4.4mm, Pitch 0.65mm, IPC High Density)
footprint TSSOP-ST8_M (TSOP, 8-Leads, Body 3x4.4mm, Pitch 0.65mm, IPC Low Density)
pins: 1 ~{CS} (in), 2 SO (hiz), 3 ~{WP} (in), 4 VSS (power), 5 SI (in), 6 SCK (in), 7 ~{HOLD} (in), 8 VCC (power)

## 25LC040A-E/MS
designator U?
4K SPI Bus Serial EEPROM, 8-Pin MSOP, Extended Temperature
footprint MSOP-MS8_N (TSOP, 8-Leads, Body 3x3mm, Pitch 0.65mm, IPC Medium Density)
footprint MSOP-MS8_L (TSOP, 8-Leads, Body 3x3mm, Pitch 0.65mm, IPC High Density)
footprint MSOP-MS8_M (TSOP, 8-Leads, Body 3x3mm, Pitch 0.65mm, IPC Low Density)
pins: 1 ~{CS} (in), 2 SO (hiz), 3 ~{WP} (in), 4 VSS (power), 5 SI (in), 6 SCK (in), 7 ~{HOLD} (in), 8 VCC (power)

## 25LC040A-E/P
designator U?
4K SPI Bus Serial EEPROM, 8-Pin PDIP, Extended Temperature
footprint PDIP300-P8 (DIP, 8-Leads, Row Spacing 7.62mm, Pitch 2.54mm, Body 9.5x6.6mm)
pins: 1 ~{CS} (in), 2 SO (hiz), 3 ~{WP} (in), 4 VSS (power), 5 SI (in), 6 SCK (in), 7 ~{HOLD} (in), 8 VCC (power)

## 25LC040A-E/SN
designator U?
4K SPI Bus Serial EEPROM, 8-Pin SOIC, Extended Temperature
footprint SOIC-SN8_N (SOIC, 8-Leads, Body 4.9x3.8mm, Pitch 1.27mm, IPC Medium Density)
footprint SOIC-SN8_L (SOIC, 8-Leads, Body 4.9x3.8mm, Pitch 1.27mm, IPC High Density)
footprint SOIC-SN8_M (SOIC, 8-Leads, Body 4.9x3.8mm, Pitch 1.27mm, IPC Low Density)
pins: 1 ~{CS} (in), 2 SO (hiz), 3 ~{WP} (in), 4 VSS (power), 5 SI (in), 6 SCK (in), 7 ~{HOLD} (in), 8 VCC (power)

## 25LC040A-E/ST
designator U?
4K SPI Bus Serial EEPROM, 8-Pin TSSOP, Extended Temperature
footprint TSSOP-ST8_N (TSOP, 8-Leads, Body 3x4.4mm, Pitch 0.65mm, IPC Medium Density)
footprint TSSOP-ST8_L (TSOP, 8-Leads, Body 3x4.4mm, Pitch 0.65mm, IPC High Density)
footprint TSSOP-ST8_M (TSOP, 8-Leads, Body 3x4.4mm, Pitch 0.65mm, IPC Low Density)
pins: 1 ~{CS} (in), 2 SO (hiz), 3 ~{WP} (in), 4 VSS (power), 5 SI (in), 6 SCK (in), 7 ~{HOLD} (in), 8 VCC (power)

## 25LC040A-I/MS
designator U?
4K SPI Bus Serial EEPROM, 8-Pin MSOP, Industrial Temperature
footprint MSOP-MS8_N (TSOP, 8-Leads, Body 3x3mm, Pitch 0.65mm, IPC Medium Density)
footprint MSOP-MS8_L (TSOP, 8-Leads, Body 3x3mm, Pitch 0.65mm, IPC High Density)
footprint MSOP-MS8_M (TSOP, 8-Leads, Body 3x3mm, Pitch 0.65mm, IPC Low Density)
pins: 1 ~{CS} (in), 2 SO (hiz), 3 ~{WP} (in), 4 VSS (power), 5 SI (in), 6 SCK (in), 7 ~{HOLD} (in), 8 VCC (power)

## 25LC040A-I/P
designator U?
4K SPI Bus Serial EEPROM, 8-Pin PDIP, Industrial Temperature
footprint PDIP300-P8 (DIP, 8-Leads, Row Spacing 7.62mm, Pitch 2.54mm, Body 9.5x6.6mm)
pins: 1 ~{CS} (in), 2 SO (hiz), 3 ~{WP} (in), 4 VSS (power), 5 SI (in), 6 SCK (in), 7 ~{HOLD} (in), 8 VCC (power)

## 25LC040A-I/SN
designator U?
4K SPI Bus Serial EEPROM, 8-Pin SOIC, Industrial Temperature
footprint SOIC-SN8_N (SOIC, 8-Leads, Body 4.9x3.8mm, Pitch 1.27mm, IPC Medium Density)
footprint SOIC-SN8_L (SOIC, 8-Leads, Body 4.9x3.8mm, Pitch 1.27mm, IPC High Density)
footprint SOIC-SN8_M (SOIC, 8-Leads, Body 4.9x3.8mm, Pitch 1.27mm, IPC Low Density)
pins: 1 ~{CS} (in), 2 SO (hiz), 3 ~{WP} (in), 4 VSS (power), 5 SI (in), 6 SCK (in), 7 ~{HOLD} (in), 8 VCC (power)

## 25LC040A-I/ST
designator U?
4K SPI Bus Serial EEPROM, 8-Pin TSSOP, Industrial Temperature
footprint TSSOP-ST8_N (TSOP, 8-Leads, Body 3x4.4mm, Pitch 0.65mm, IPC Medium Density)
footprint TSSOP-ST8_L (TSOP, 8-Leads, Body 3x4.4mm, Pitch 0.65mm, IPC High Density)
footprint TSSOP-ST8_M (TSOP, 8-Leads, Body 3x4.4mm, Pitch 0.65mm, IPC Low Density)
pins: 1 ~{CS} (in), 2 SO (hiz), 3 ~{WP} (in), 4 VSS (power), 5 SI (in), 6 SCK (in), 7 ~{HOLD} (in), 8 VCC (power)

## 25LC040AT-E/MC
designator U?
4K SPI Bus Serial EEPROM, 8-Pin DFN, Extended Temperature, Tape and Reel
footprint DFN-MC8 (SON, 8-Leads, Body 2x3mm, Pitch 0.5mm, Microchip Recommended)
pins: 1 ~{CS} (in), 2 SO (hiz), 3 ~{WP} (in), 4 VSS (power), 5 SI (in), 6 SCK (in), 7 ~{HOLD} (in), 8 VCC (power), 9 EP

## 25LC040AT-E/MS
designator U?
4K SPI Bus Serial EEPROM, 8-Pin MSOP, Extended Temperature, Tape and Reel
footprint MSOP-MS8_N (TSOP, 8-Leads, Body 3x3mm, Pitch 0.65mm, IPC Medium Density)
footprint MSOP-MS8_L (TSOP, 8-Leads, Body 3x3mm, Pitch 0.65mm, IPC High Density)
footprint MSOP-MS8_M (TSOP, 8-Leads, Body 3x3mm, Pitch 0.65mm, IPC Low Density)
pins: 1 ~{CS} (in), 2 SO (hiz), 3 ~{WP} (in), 4 VSS (power), 5 SI (in), 6 SCK (in), 7 ~{HOLD} (in), 8 VCC (power)

## 25LC040AT-E/OT
designator U?
4K SPI Bus Serial EEPROM, 6-Pin SOT-23, Extended Temperature, Tape and Reel
footprint SOT-23-OT6_N (SOT23, 6-Leads, Body 2.9x1.6mm, Pitch 0.95mm, Lead Span 2.7mm, IPC Medium Density)
footprint SOT-23-OT6_L (SOT23, 6-Leads, Body 2.9x1.6mm, Pitch 0.95mm, Lead Span 2.7mm, IPC High Density)
footprint SOT-23-OT6_M (SOT23, 6-Leads, Body 2.9x1.6mm, Pitch 0.95mm, Lead Span 2.7mm, IPC Low Density)
pins: 1 SCK (in), 2 VSS (power), 3 SI (in), 4 SO (hiz), 5 ~{CS} (in), 6 VDD (power)

## 25LC040AT-E/SN
designator U?
4K SPI Bus Serial EEPROM, 8-Pin SOIC, Extended Temperature, Tape and Reel
footprint SOIC-SN8_N (SOIC, 8-Leads, Body 4.9x3.8mm, Pitch 1.27mm, IPC Medium Density)
footprint SOIC-SN8_L (SOIC, 8-Leads, Body 4.9x3.8mm, Pitch 1.27mm, IPC High Density)
footprint SOIC-SN8_M (SOIC, 8-Leads, Body 4.9x3.8mm, Pitch 1.27mm, IPC Low Density)
pins: 1 ~{CS} (in), 2 SO (hiz), 3 ~{WP} (in), 4 VSS (power), 5 SI (in), 6 SCK (in), 7 ~{HOLD} (in), 8 VCC (power)

## 25LC040AT-E/ST
designator U?
4K SPI Bus Serial EEPROM, 8-Pin TSSOP, Extended Temperature, Tape and Reel
footprint TSSOP-ST8_N (TSOP, 8-Leads, Body 3x4.4mm, Pitch 0.65mm, IPC Medium Density)
footprint TSSOP-ST8_L (TSOP, 8-Leads, Body 3x4.4mm, Pitch 0.65mm, IPC High Density)
footprint TSSOP-ST8_M (TSOP, 8-Leads, Body 3x4.4mm, Pitch 0.65mm, IPC Low Density)
pins: 1 ~{CS} (in), 2 SO (hiz), 3 ~{WP} (in), 4 VSS (power), 5 SI (in), 6 SCK (in), 7 ~{HOLD} (in), 8 VCC (power)

## 25LC040AT-I/MC
designator U?
4K SPI Bus Serial EEPROM, 8-Pin DFN, Industrial Temperature, Tape and Reel
footprint DFN-MC8 (SON, 8-Leads, Body 2x3mm, Pitch 0.5mm, Microchip Recommended)
pins: 1 ~{CS} (in), 2 SO (hiz), 3 ~{WP} (in), 4 VSS (power), 5 SI (in), 6 SCK (in), 7 ~{HOLD} (in), 8 VCC (power), 9 EP

## 25LC040AT-I/MS
designator U?
4K SPI Bus Serial EEPROM, 8-Pin MSOP, Industrial Temperature, Tape and Reel
footprint MSOP-MS8_N (TSOP, 8-Leads, Body 3x3mm, Pitch 0.65mm, IPC Medium Density)
footprint MSOP-MS8_L (TSOP, 8-Leads, Body 3x3mm, Pitch 0.65mm, IPC High Density)
footprint MSOP-MS8_M (TSOP, 8-Leads, Body 3x3mm, Pitch 0.65mm, IPC Low Density)
pins: 1 ~{CS} (in), 2 SO (hiz), 3 ~{WP} (in), 4 VSS (power), 5 SI (in), 6 SCK (in), 7 ~{HOLD} (in), 8 VCC (power)

## 25LC040AT-I/OT
designator U?
4K SPI Bus Serial EEPROM, 6-Pin SOT-23, Industrial Temperature, Tape and Reel
footprint SOT-23-OT6_N (SOT23, 6-Leads, Body 2.9x1.6mm, Pitch 0.95mm, Lead Span 2.7mm, IPC Medium Density)
footprint SOT-23-OT6_L (SOT23, 6-Leads, Body 2.9x1.6mm, Pitch 0.95mm, Lead Span 2.7mm, IPC High Density)
footprint SOT-23-OT6_M (SOT23, 6-Leads, Body 2.9x1.6mm, Pitch 0.95mm, Lead Span 2.7mm, IPC Low Density)
pins: 1 SCK (in), 2 VSS (power), 3 SI (in), 4 SO (hiz), 5 ~{CS} (in), 6 VDD (power)

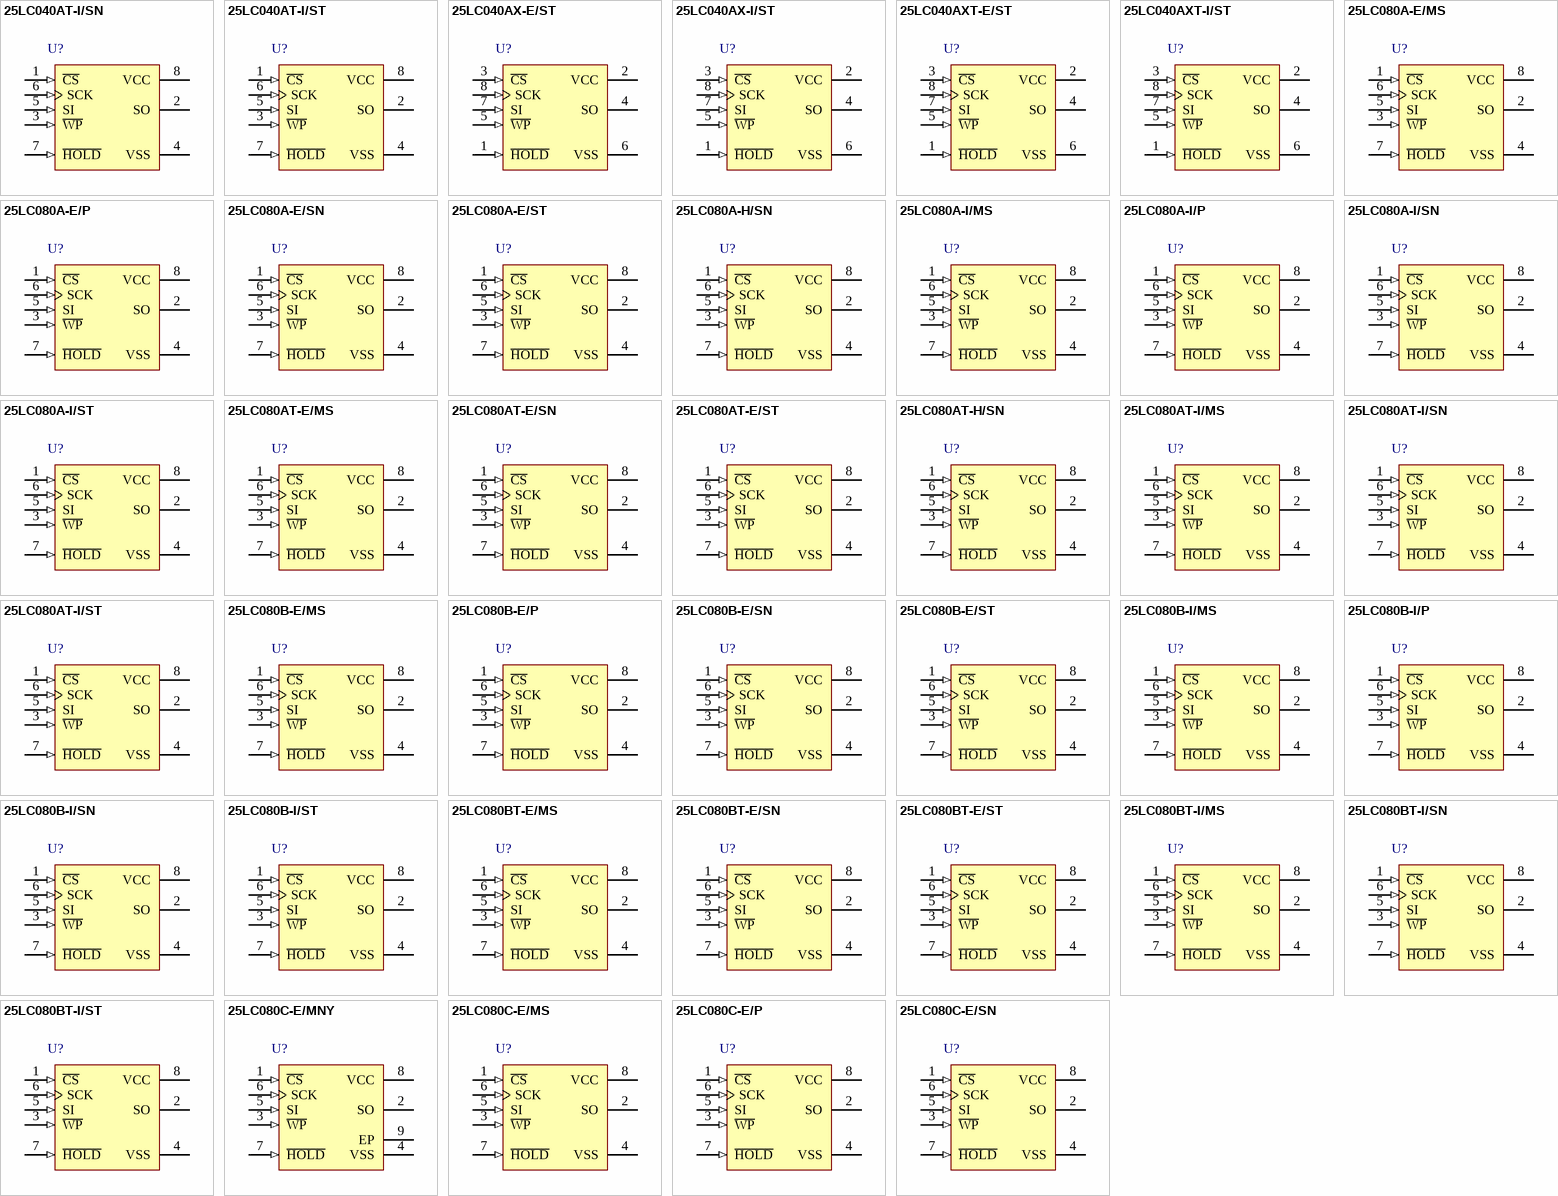
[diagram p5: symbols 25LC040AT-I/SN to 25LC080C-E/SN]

## 25LC040AT-I/SN
designator U?
4K SPI Bus Serial EEPROM, 8-Pin SOIC, Industrial Temperature, Tape and Reel
footprint SOIC-SN8_N (SOIC, 8-Leads, Body 4.9x3.8mm, Pitch 1.27mm, IPC Medium Density)
footprint SOIC-SN8_L (SOIC, 8-Leads, Body 4.9x3.8mm, Pitch 1.27mm, IPC High Density)
footprint SOIC-SN8_M (SOIC, 8-Leads, Body 4.9x3.8mm, Pitch 1.27mm, IPC Low Density)
pins: 1 ~{CS} (in), 2 SO (hiz), 3 ~{WP} (in), 4 VSS (power), 5 SI (in), 6 SCK (in), 7 ~{HOLD} (in), 8 VCC (power)

## 25LC040AT-I/ST
designator U?
4K SPI Bus Serial EEPROM, 8-Pin TSSOP, Industrial Temperature, Tape and Reel
footprint TSSOP-ST8_N (TSOP, 8-Leads, Body 3x4.4mm, Pitch 0.65mm, IPC Medium Density)
footprint TSSOP-ST8_L (TSOP, 8-Leads, Body 3x4.4mm, Pitch 0.65mm, IPC High Density)
footprint TSSOP-ST8_M (TSOP, 8-Leads, Body 3x4.4mm, Pitch 0.65mm, IPC Low Density)
pins: 1 ~{CS} (in), 2 SO (hiz), 3 ~{WP} (in), 4 VSS (power), 5 SI (in), 6 SCK (in), 7 ~{HOLD} (in), 8 VCC (power)

## 25LC040AX-E/ST
designator U?
4K SPI Bus Serial EEPROM, 8-Pin TSSOP, Extended Temperature
footprint TSSOP-ST8_N (TSOP, 8-Leads, Body 3x4.4mm, Pitch 0.65mm, IPC Medium Density)
footprint TSSOP-ST8_L (TSOP, 8-Leads, Body 3x4.4mm, Pitch 0.65mm, IPC High Density)
footprint TSSOP-ST8_M (TSOP, 8-Leads, Body 3x4.4mm, Pitch 0.65mm, IPC Low Density)
pins: 1 ~{HOLD} (in), 2 VCC (power), 3 ~{CS} (in), 4 SO (hiz), 5 ~{WP} (in), 6 VSS (power), 7 SI (in), 8 SCK (in)

## 25LC040AX-I/ST
designator U?
4K SPI Bus Serial EEPROM, 8-Pin TSSOP, Industrial Temperature
footprint TSSOP-ST8_N (TSOP, 8-Leads, Body 3x4.4mm, Pitch 0.65mm, IPC Medium Density)
footprint TSSOP-ST8_L (TSOP, 8-Leads, Body 3x4.4mm, Pitch 0.65mm, IPC High Density)
footprint TSSOP-ST8_M (TSOP, 8-Leads, Body 3x4.4mm, Pitch 0.65mm, IPC Low Density)
pins: 1 ~{HOLD} (in), 2 VCC (power), 3 ~{CS} (in), 4 SO (hiz), 5 ~{WP} (in), 6 VSS (power), 7 SI (in), 8 SCK (in)

## 25LC040AXT-E/ST
designator U?
4K SPI Bus Serial EEPROM, 8-Pin TSSOP, Extended Temperature, Tape and Reel
footprint TSSOP-ST8_N (TSOP, 8-Leads, Body 3x4.4mm, Pitch 0.65mm, IPC Medium Density)
footprint TSSOP-ST8_L (TSOP, 8-Leads, Body 3x4.4mm, Pitch 0.65mm, IPC High Density)
footprint TSSOP-ST8_M (TSOP, 8-Leads, Body 3x4.4mm, Pitch 0.65mm, IPC Low Density)
pins: 1 ~{HOLD} (in), 2 VCC (power), 3 ~{CS} (in), 4 SO (hiz), 5 ~{WP} (in), 6 VSS (power), 7 SI (in), 8 SCK (in)

## 25LC040AXT-I/ST
designator U?
4K SPI Bus Serial EEPROM, 8-Pin TSSOP, Industrial Temperature, Tape and Reel
footprint TSSOP-ST8_N (TSOP, 8-Leads, Body 3x4.4mm, Pitch 0.65mm, IPC Medium Density)
footprint TSSOP-ST8_L (TSOP, 8-Leads, Body 3x4.4mm, Pitch 0.65mm, IPC High Density)
footprint TSSOP-ST8_M (TSOP, 8-Leads, Body 3x4.4mm, Pitch 0.65mm, IPC Low Density)
pins: 1 ~{HOLD} (in), 2 VCC (power), 3 ~{CS} (in), 4 SO (hiz), 5 ~{WP} (in), 6 VSS (power), 7 SI (in), 8 SCK (in)

## 25LC080A-E/MS
designator U?
8K SPI Bus Serial EEPROM, 8-Pin MSOP, Extended Temperature; ComponentAvailability: Unknown. Contact manufacturer to determine status.
footprint MSOP-MS8_N (TSOP, 8-Leads, Body 3x3mm, Pitch 0.65mm, IPC Medium Density)
footprint MSOP-MS8_L (TSOP, 8-Leads, Body 3x3mm, Pitch 0.65mm, IPC High Density)
footprint MSOP-MS8_M (TSOP, 8-Leads, Body 3x3mm, Pitch 0.65mm, IPC Low Density)
pins: 1 ~{CS} (in), 2 SO (hiz), 3 ~{WP} (in), 4 VSS (power), 5 SI (in), 6 SCK (in), 7 ~{HOLD} (in), 8 VCC (power)

## 25LC080A-E/P
designator U?
8K SPI Bus Serial EEPROM, 8-Pin PDIP, Extended Temperature; ComponentAvailability: Unknown. Contact manufacturer to determine status.
footprint PDIP300-P8 (DIP, 8-Leads, Row Spacing 7.62mm, Pitch 2.54mm, Body 9.5x6.6mm)
pins: 1 ~{CS} (in), 2 SO (hiz), 3 ~{WP} (in), 4 VSS (power), 5 SI (in), 6 SCK (in), 7 ~{HOLD} (in), 8 VCC (power)

## 25LC080A-E/SN
designator U?
8K SPI Bus Serial EEPROM, 8-Pin SOIC, Extended Temperature; ComponentAvailability: Unknown. Contact manufacturer to determine status.
footprint SOIC-SN8_N (SOIC, 8-Leads, Body 4.9x3.8mm, Pitch 1.27mm, IPC Medium Density)
footprint SOIC-SN8_L (SOIC, 8-Leads, Body 4.9x3.8mm, Pitch 1.27mm, IPC High Density)
footprint SOIC-SN8_M (SOIC, 8-Leads, Body 4.9x3.8mm, Pitch 1.27mm, IPC Low Density)
pins: 1 ~{CS} (in), 2 SO (hiz), 3 ~{WP} (in), 4 VSS (power), 5 SI (in), 6 SCK (in), 7 ~{HOLD} (in), 8 VCC (power)

## 25LC080A-E/ST
designator U?
8K SPI Bus Serial EEPROM, 8-Pin TSSOP, Extended Temperature; ComponentAvailability: Unknown. Contact manufacturer to determine status.
footprint TSSOP-ST8_N (TSOP, 8-Leads, Body 3x4.4mm, Pitch 0.65mm, IPC Medium Density)
footprint TSSOP-ST8_L (TSOP, 8-Leads, Body 3x4.4mm, Pitch 0.65mm, IPC High Density)
footprint TSSOP-ST8_M (TSOP, 8-Leads, Body 3x4.4mm, Pitch 0.65mm, IPC Low Density)
pins: 1 ~{CS} (in), 2 SO (hiz), 3 ~{WP} (in), 4 VSS (power), 5 SI (in), 6 SCK (in), 7 ~{HOLD} (in), 8 VCC (power)

## 25LC080A-H/SN
designator U?
8K SPI Bus Serial EEPROM, 8-Pin SOIC; ComponentAvailability: Unknown. Contact manufacturer to determine status.
footprint SOIC-SN8_N (SOIC, 8-Leads, Body 4.9x3.8mm, Pitch 1.27mm, IPC Medium Density)
footprint SOIC-SN8_L (SOIC, 8-Leads, Body 4.9x3.8mm, Pitch 1.27mm, IPC High Density)
footprint SOIC-SN8_M (SOIC, 8-Leads, Body 4.9x3.8mm, Pitch 1.27mm, IPC Low Density)
pins: 1 ~{CS} (in), 2 SO (hiz), 3 ~{WP} (in), 4 VSS (power), 5 SI (in), 6 SCK (in), 7 ~{HOLD} (in), 8 VCC (power)

## 25LC080A-I/MS
designator U?
8K SPI Bus Serial EEPROM, 8-Pin MSOP, Industrial Temperature; ComponentAvailability: Unknown. Contact manufacturer to determine status.
footprint MSOP-MS8_N (TSOP, 8-Leads, Body 3x3mm, Pitch 0.65mm, IPC Medium Density)
footprint MSOP-MS8_L (TSOP, 8-Leads, Body 3x3mm, Pitch 0.65mm, IPC High Density)
footprint MSOP-MS8_M (TSOP, 8-Leads, Body 3x3mm, Pitch 0.65mm, IPC Low Density)
pins: 1 ~{CS} (in), 2 SO (hiz), 3 ~{WP} (in), 4 VSS (power), 5 SI (in), 6 SCK (in), 7 ~{HOLD} (in), 8 VCC (power)

## 25LC080A-I/P
designator U?
8K SPI Bus Serial EEPROM, 8-Pin PDIP, Industrial Temperature; ComponentAvailability: Unknown. Contact manufacturer to determine status.
footprint PDIP300-P8 (DIP, 8-Leads, Row Spacing 7.62mm, Pitch 2.54mm, Body 9.5x6.6mm)
pins: 1 ~{CS} (in), 2 SO (hiz), 3 ~{WP} (in), 4 VSS (power), 5 SI (in), 6 SCK (in), 7 ~{HOLD} (in), 8 VCC (power)

## 25LC080A-I/SN
designator U?
8K SPI Bus Serial EEPROM, 8-Pin SOIC, Industrial Temperature; ComponentAvailability: Unknown. Contact manufacturer to determine status.
footprint SOIC-SN8_N (SOIC, 8-Leads, Body 4.9x3.8mm, Pitch 1.27mm, IPC Medium Density)
footprint SOIC-SN8_L (SOIC, 8-Leads, Body 4.9x3.8mm, Pitch 1.27mm, IPC High Density)
footprint SOIC-SN8_M (SOIC, 8-Leads, Body 4.9x3.8mm, Pitch 1.27mm, IPC Low Density)
pins: 1 ~{CS} (in), 2 SO (hiz), 3 ~{WP} (in), 4 VSS (power), 5 SI (in), 6 SCK (in), 7 ~{HOLD} (in), 8 VCC (power)

## 25LC080A-I/ST
designator U?
8K SPI Bus Serial EEPROM, 8-Pin TSSOP, Industrial Temperature; ComponentAvailability: Unknown. Contact manufacturer to determine status.
footprint TSSOP-ST8_N (TSOP, 8-Leads, Body 3x4.4mm, Pitch 0.65mm, IPC Medium Density)
footprint TSSOP-ST8_L (TSOP, 8-Leads, Body 3x4.4mm, Pitch 0.65mm, IPC High Density)
footprint TSSOP-ST8_M (TSOP, 8-Leads, Body 3x4.4mm, Pitch 0.65mm, IPC Low Density)
pins: 1 ~{CS} (in), 2 SO (hiz), 3 ~{WP} (in), 4 VSS (power), 5 SI (in), 6 SCK (in), 7 ~{HOLD} (in), 8 VCC (power)

## 25LC080AT-E/MS
designator U?
8K SPI Bus Serial EEPROM, 8-Pin MSOP, Extended Temperature, Tape and Reel; ComponentAvailability: Unknown. Contact manufacturer to determine status.
footprint MSOP-MS8_N (TSOP, 8-Leads, Body 3x3mm, Pitch 0.65mm, IPC Medium Density)
footprint MSOP-MS8_L (TSOP, 8-Leads, Body 3x3mm, Pitch 0.65mm, IPC High Density)
footprint MSOP-MS8_M (TSOP, 8-Leads, Body 3x3mm, Pitch 0.65mm, IPC Low Density)
pins: 1 ~{CS} (in), 2 SO (hiz), 3 ~{WP} (in), 4 VSS (power), 5 SI (in), 6 SCK (in), 7 ~{HOLD} (in), 8 VCC (power)

## 25LC080AT-E/SN
designator U?
8K SPI Bus Serial EEPROM, 8-Pin SOIC, Extended Temperature, Tape and Reel; ComponentAvailability: Unknown. Contact manufacturer to determine status.
footprint SOIC-SN8_N (SOIC, 8-Leads, Body 4.9x3.8mm, Pitch 1.27mm, IPC Medium Density)
footprint SOIC-SN8_L (SOIC, 8-Leads, Body 4.9x3.8mm, Pitch 1.27mm, IPC High Density)
footprint SOIC-SN8_M (SOIC, 8-Leads, Body 4.9x3.8mm, Pitch 1.27mm, IPC Low Density)
pins: 1 ~{CS} (in), 2 SO (hiz), 3 ~{WP} (in), 4 VSS (power), 5 SI (in), 6 SCK (in), 7 ~{HOLD} (in), 8 VCC (power)

## 25LC080AT-E/ST
designator U?
8K SPI Bus Serial EEPROM, 8-Pin TSSOP, Extended Temperature, Tape and Reel; ComponentAvailability: Unknown. Contact manufacturer to determine status.
footprint TSSOP-ST8_N (TSOP, 8-Leads, Body 3x4.4mm, Pitch 0.65mm, IPC Medium Density)
footprint TSSOP-ST8_L (TSOP, 8-Leads, Body 3x4.4mm, Pitch 0.65mm, IPC High Density)
footprint TSSOP-ST8_M (TSOP, 8-Leads, Body 3x4.4mm, Pitch 0.65mm, IPC Low Density)
pins: 1 ~{CS} (in), 2 SO (hiz), 3 ~{WP} (in), 4 VSS (power), 5 SI (in), 6 SCK (in), 7 ~{HOLD} (in), 8 VCC (power)

## 25LC080AT-H/SN
designator U?
8K SPI Bus Serial EEPROM, 8-Pin SOIC, Tape and Reel; ComponentAvailability: Unknown. Contact manufacturer to determine status.
footprint SOIC-SN8_N (SOIC, 8-Leads, Body 4.9x3.8mm, Pitch 1.27mm, IPC Medium Density)
footprint SOIC-SN8_L (SOIC, 8-Leads, Body 4.9x3.8mm, Pitch 1.27mm, IPC High Density)
footprint SOIC-SN8_M (SOIC, 8-Leads, Body 4.9x3.8mm, Pitch 1.27mm, IPC Low Density)
pins: 1 ~{CS} (in), 2 SO (hiz), 3 ~{WP} (in), 4 VSS (power), 5 SI (in), 6 SCK (in), 7 ~{HOLD} (in), 8 VCC (power)

## 25LC080AT-I/MS
designator U?
8K SPI Bus Serial EEPROM, 8-Pin MSOP, Industrial Temperature, Tape and Reel; ComponentAvailability: Unknown. Contact manufacturer to determine status.
footprint MSOP-MS8_N (TSOP, 8-Leads, Body 3x3mm, Pitch 0.65mm, IPC Medium Density)
footprint MSOP-MS8_L (TSOP, 8-Leads, Body 3x3mm, Pitch 0.65mm, IPC High Density)
footprint MSOP-MS8_M (TSOP, 8-Leads, Body 3x3mm, Pitch 0.65mm, IPC Low Density)
pins: 1 ~{CS} (in), 2 SO (hiz), 3 ~{WP} (in), 4 VSS (power), 5 SI (in), 6 SCK (in), 7 ~{HOLD} (in), 8 VCC (power)

## 25LC080AT-I/SN
designator U?
8K SPI Bus Serial EEPROM, 8-Pin SOIC, Industrial Temperature, Tape and Reel; ComponentAvailability: Unknown. Contact manufacturer to determine status.
footprint SOIC-SN8_N (SOIC, 8-Leads, Body 4.9x3.8mm, Pitch 1.27mm, IPC Medium Density)
footprint SOIC-SN8_L (SOIC, 8-Leads, Body 4.9x3.8mm, Pitch 1.27mm, IPC High Density)
footprint SOIC-SN8_M (SOIC, 8-Leads, Body 4.9x3.8mm, Pitch 1.27mm, IPC Low Density)
pins: 1 ~{CS} (in), 2 SO (hiz), 3 ~{WP} (in), 4 VSS (power), 5 SI (in), 6 SCK (in), 7 ~{HOLD} (in), 8 VCC (power)

## 25LC080AT-I/ST
designator U?
8K SPI Bus Serial EEPROM, 8-Pin TSSOP, Industrial Temperature, Tape and Reel; ComponentAvailability: Unknown. Contact manufacturer to determine status.
footprint TSSOP-ST8_N (TSOP, 8-Leads, Body 3x4.4mm, Pitch 0.65mm, IPC Medium Density)
footprint TSSOP-ST8_L (TSOP, 8-Leads, Body 3x4.4mm, Pitch 0.65mm, IPC High Density)
footprint TSSOP-ST8_M (TSOP, 8-Leads, Body 3x4.4mm, Pitch 0.65mm, IPC Low Density)
pins: 1 ~{CS} (in), 2 SO (hiz), 3 ~{WP} (in), 4 VSS (power), 5 SI (in), 6 SCK (in), 7 ~{HOLD} (in), 8 VCC (power)

## 25LC080B-E/MS
designator U?
8K SPI Bus Serial EEPROM, 8-Pin MSOP, Extended Temperature; ComponentAvailability: Unknown. Contact manufacturer to determine status.
footprint MSOP-MS8_N (TSOP, 8-Leads, Body 3x3mm, Pitch 0.65mm, IPC Medium Density)
footprint MSOP-MS8_L (TSOP, 8-Leads, Body 3x3mm, Pitch 0.65mm, IPC High Density)
footprint MSOP-MS8_M (TSOP, 8-Leads, Body 3x3mm, Pitch 0.65mm, IPC Low Density)
pins: 1 ~{CS} (in), 2 SO (hiz), 3 ~{WP} (in), 4 VSS (power), 5 SI (in), 6 SCK (in), 7 ~{HOLD} (in), 8 VCC (power)

## 25LC080B-E/P
designator U?
8K SPI Bus Serial EEPROM, 8-Pin PDIP, Extended Temperature; ComponentAvailability: Unknown. Contact manufacturer to determine status.
footprint PDIP300-P8 (DIP, 8-Leads, Row Spacing 7.62mm, Pitch 2.54mm, Body 9.5x6.6mm)
pins: 1 ~{CS} (in), 2 SO (hiz), 3 ~{WP} (in), 4 VSS (power), 5 SI (in), 6 SCK (in), 7 ~{HOLD} (in), 8 VCC (power)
